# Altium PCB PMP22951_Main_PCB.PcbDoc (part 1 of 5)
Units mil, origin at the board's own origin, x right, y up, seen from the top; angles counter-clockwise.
Board outline 6643.5 x 4153.54 mil, 6 copper layers (Top Layer, Signal Layer 1, Signal Layer 2, Signal Layer 3, Signal Layer 4, Bottom Layer), stack 65.8 mil thick; 139 components, 80 nets, 687 pads, 417 vias.
Unrouted connection lines stored in the file: 2.
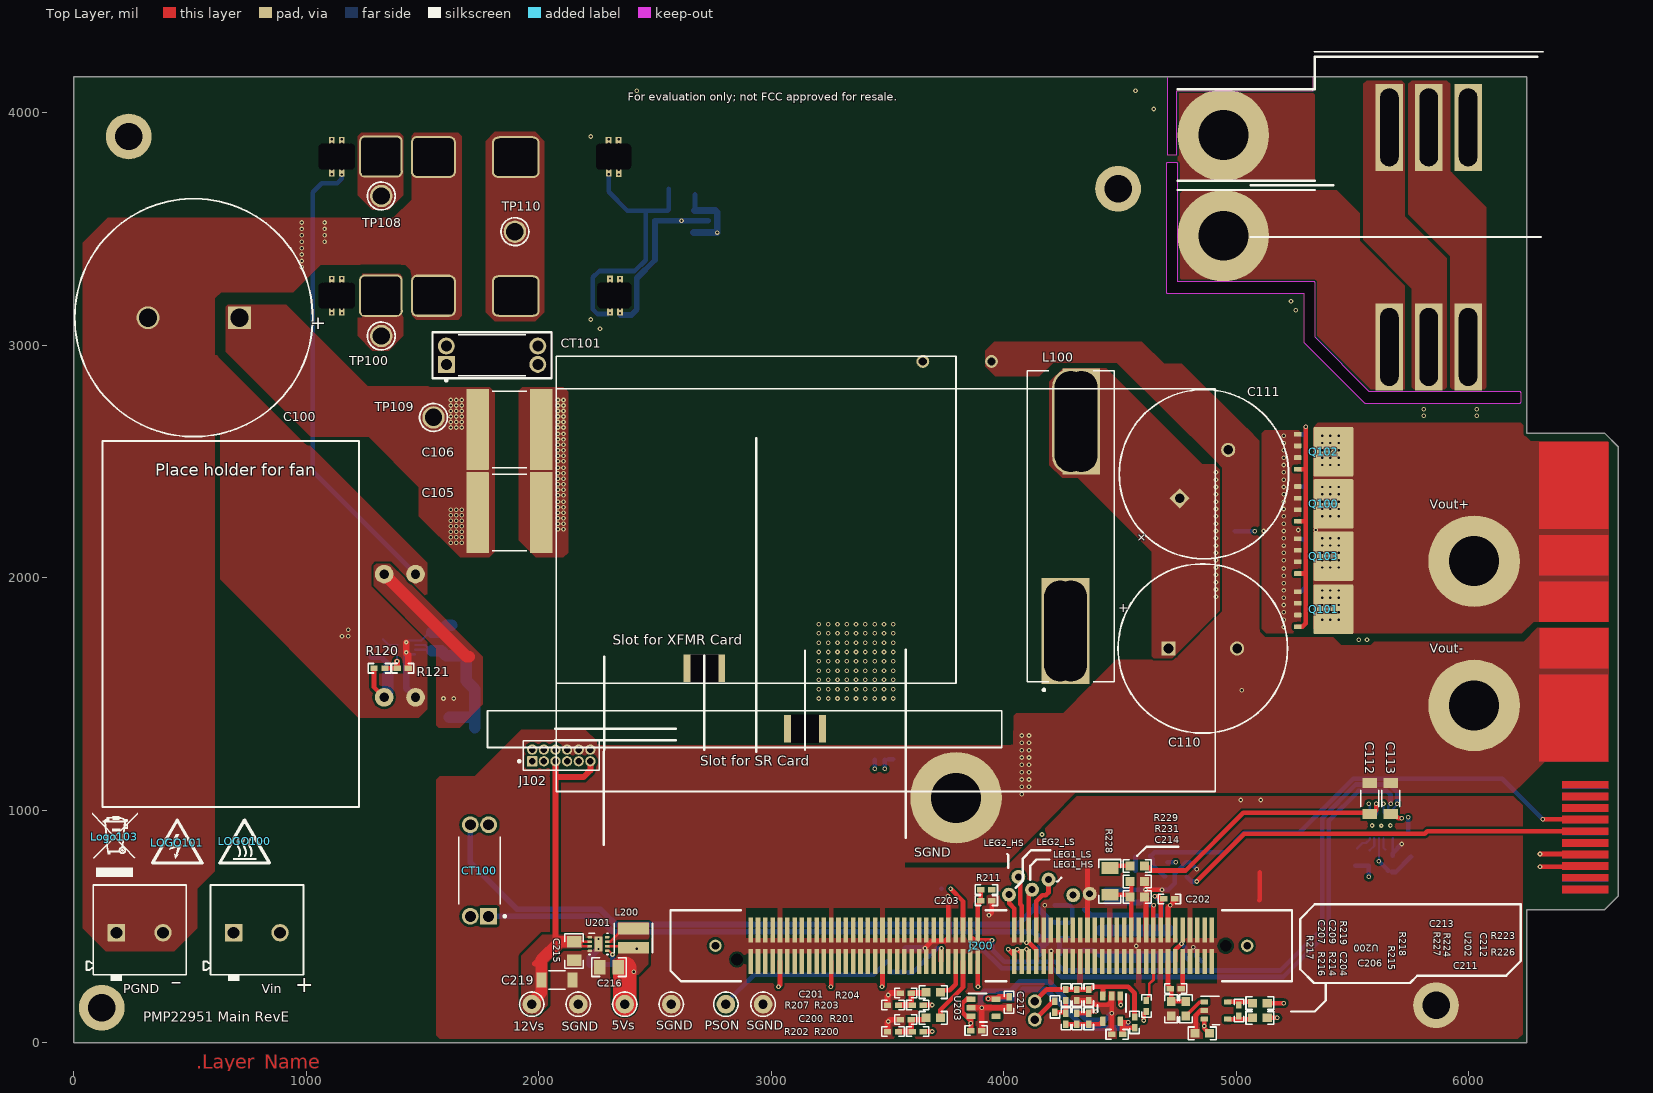
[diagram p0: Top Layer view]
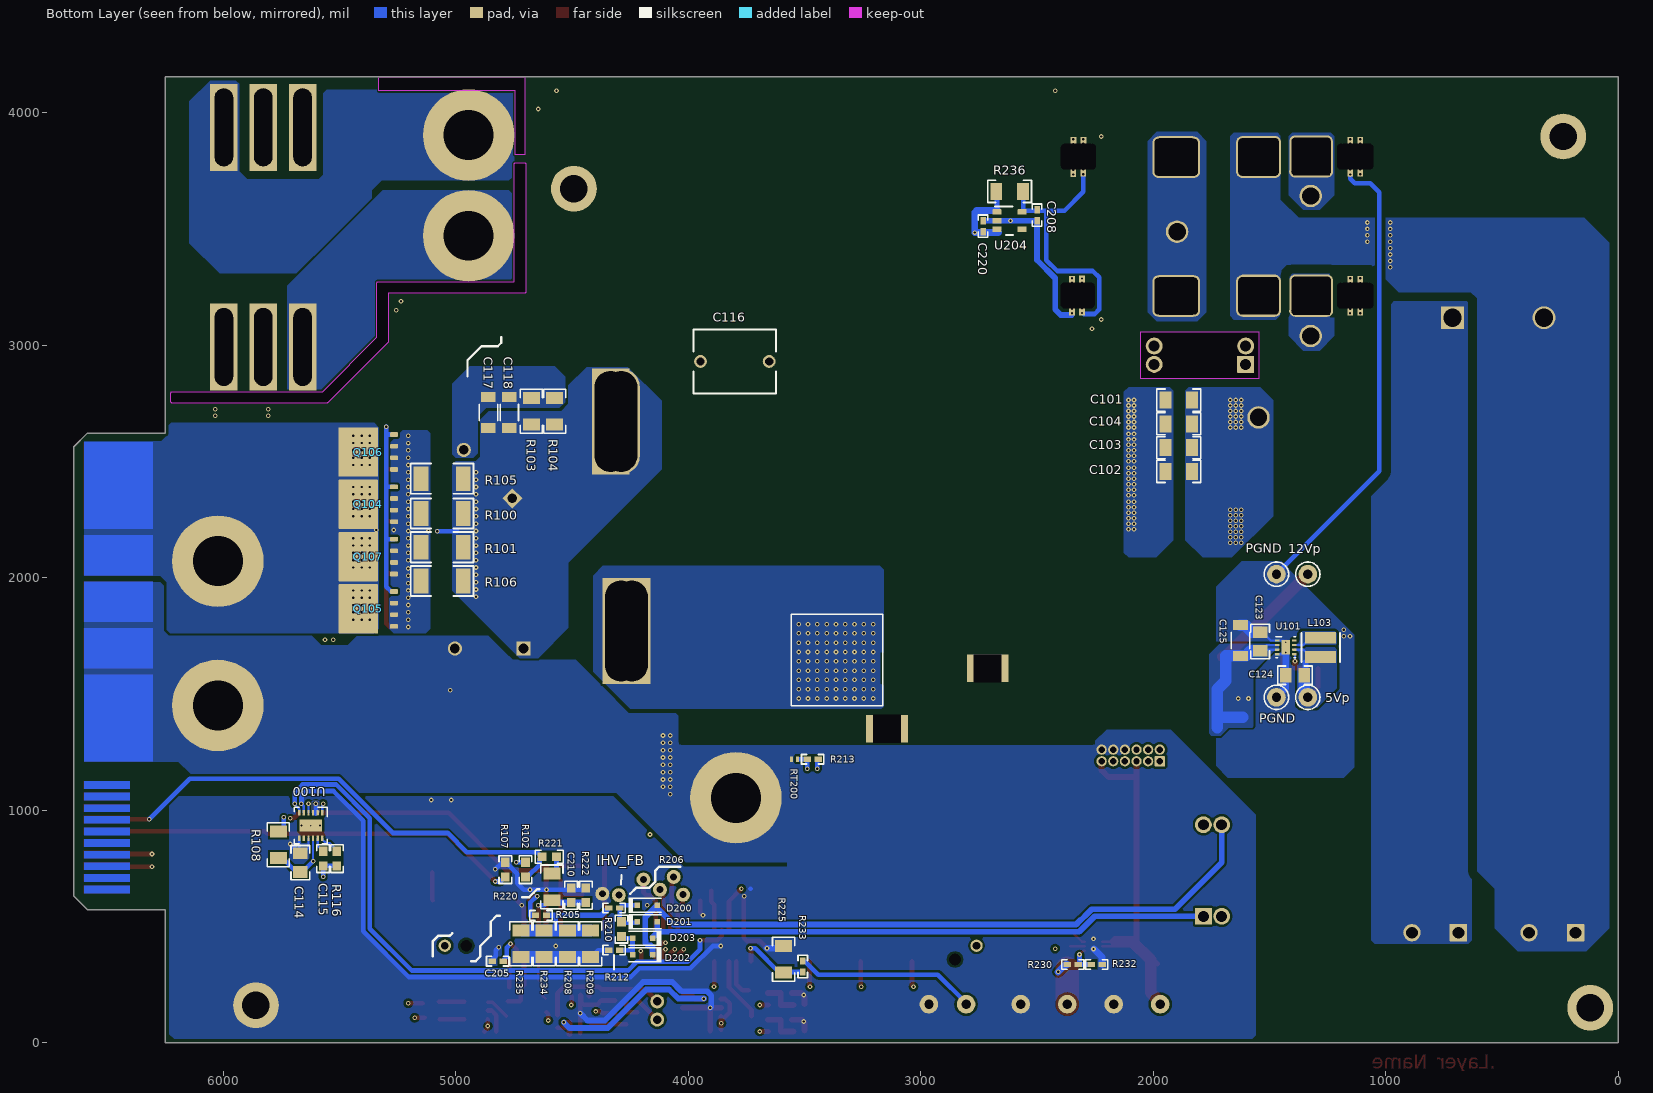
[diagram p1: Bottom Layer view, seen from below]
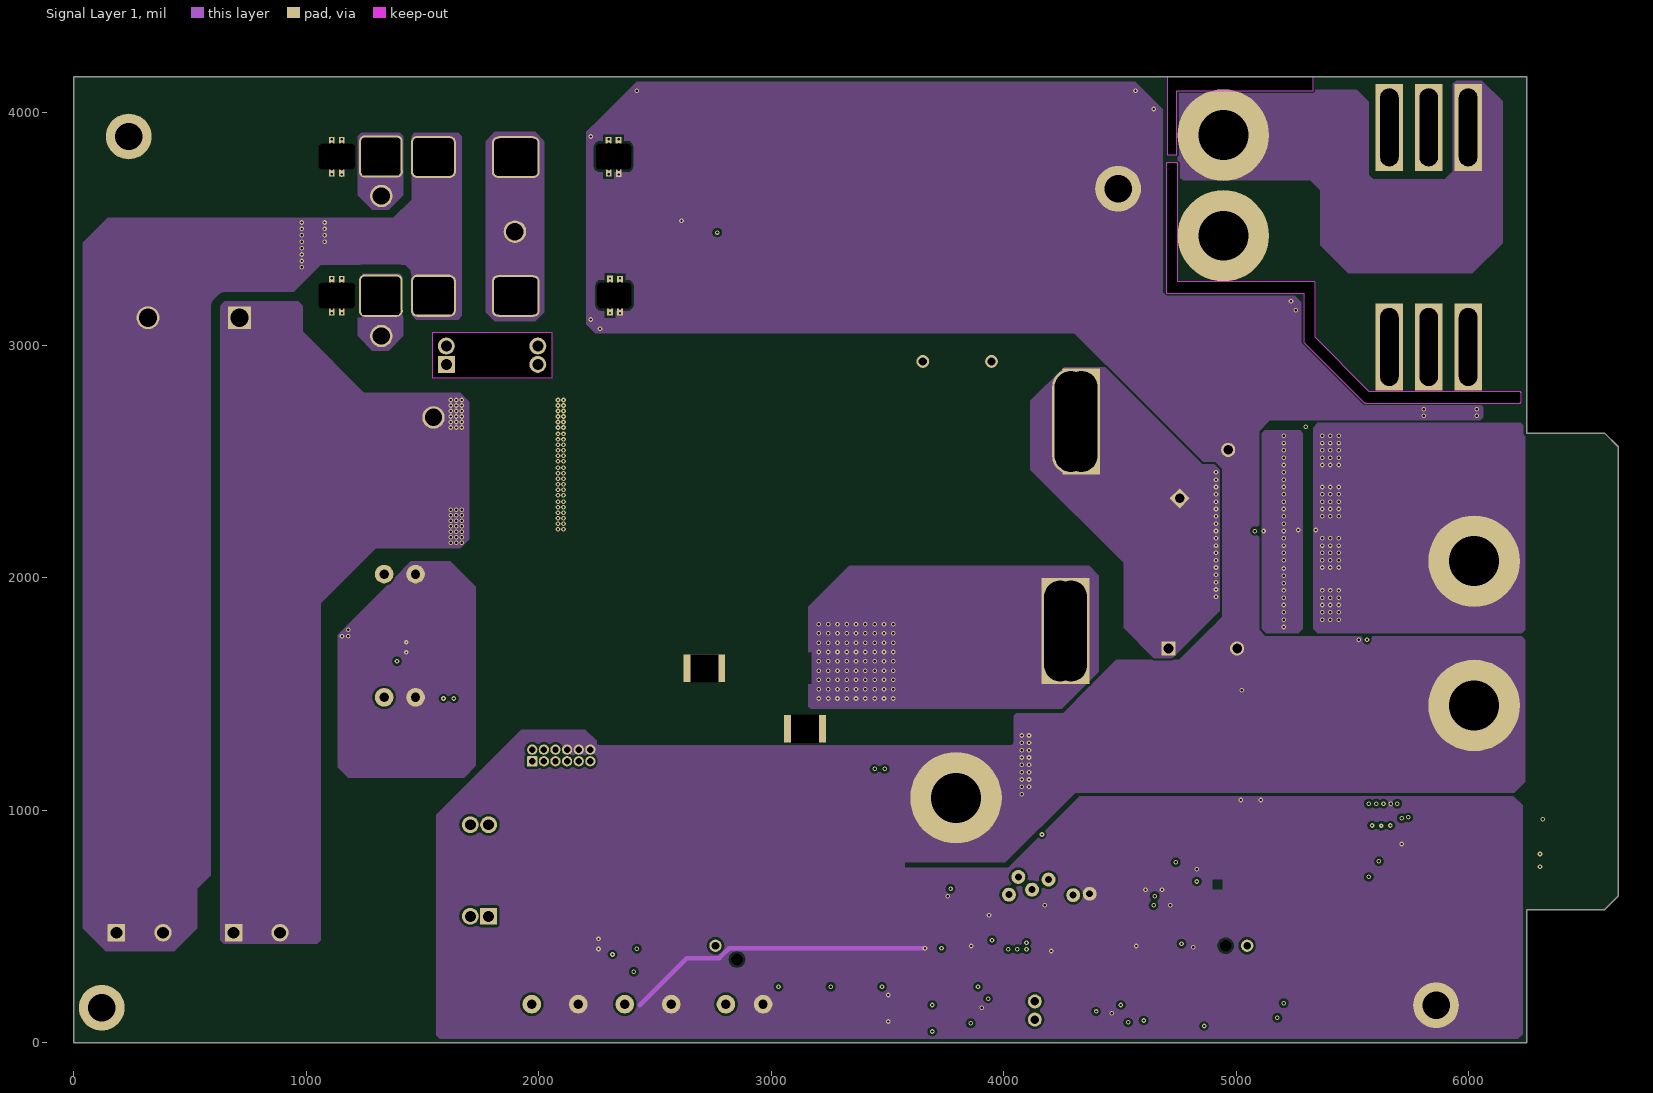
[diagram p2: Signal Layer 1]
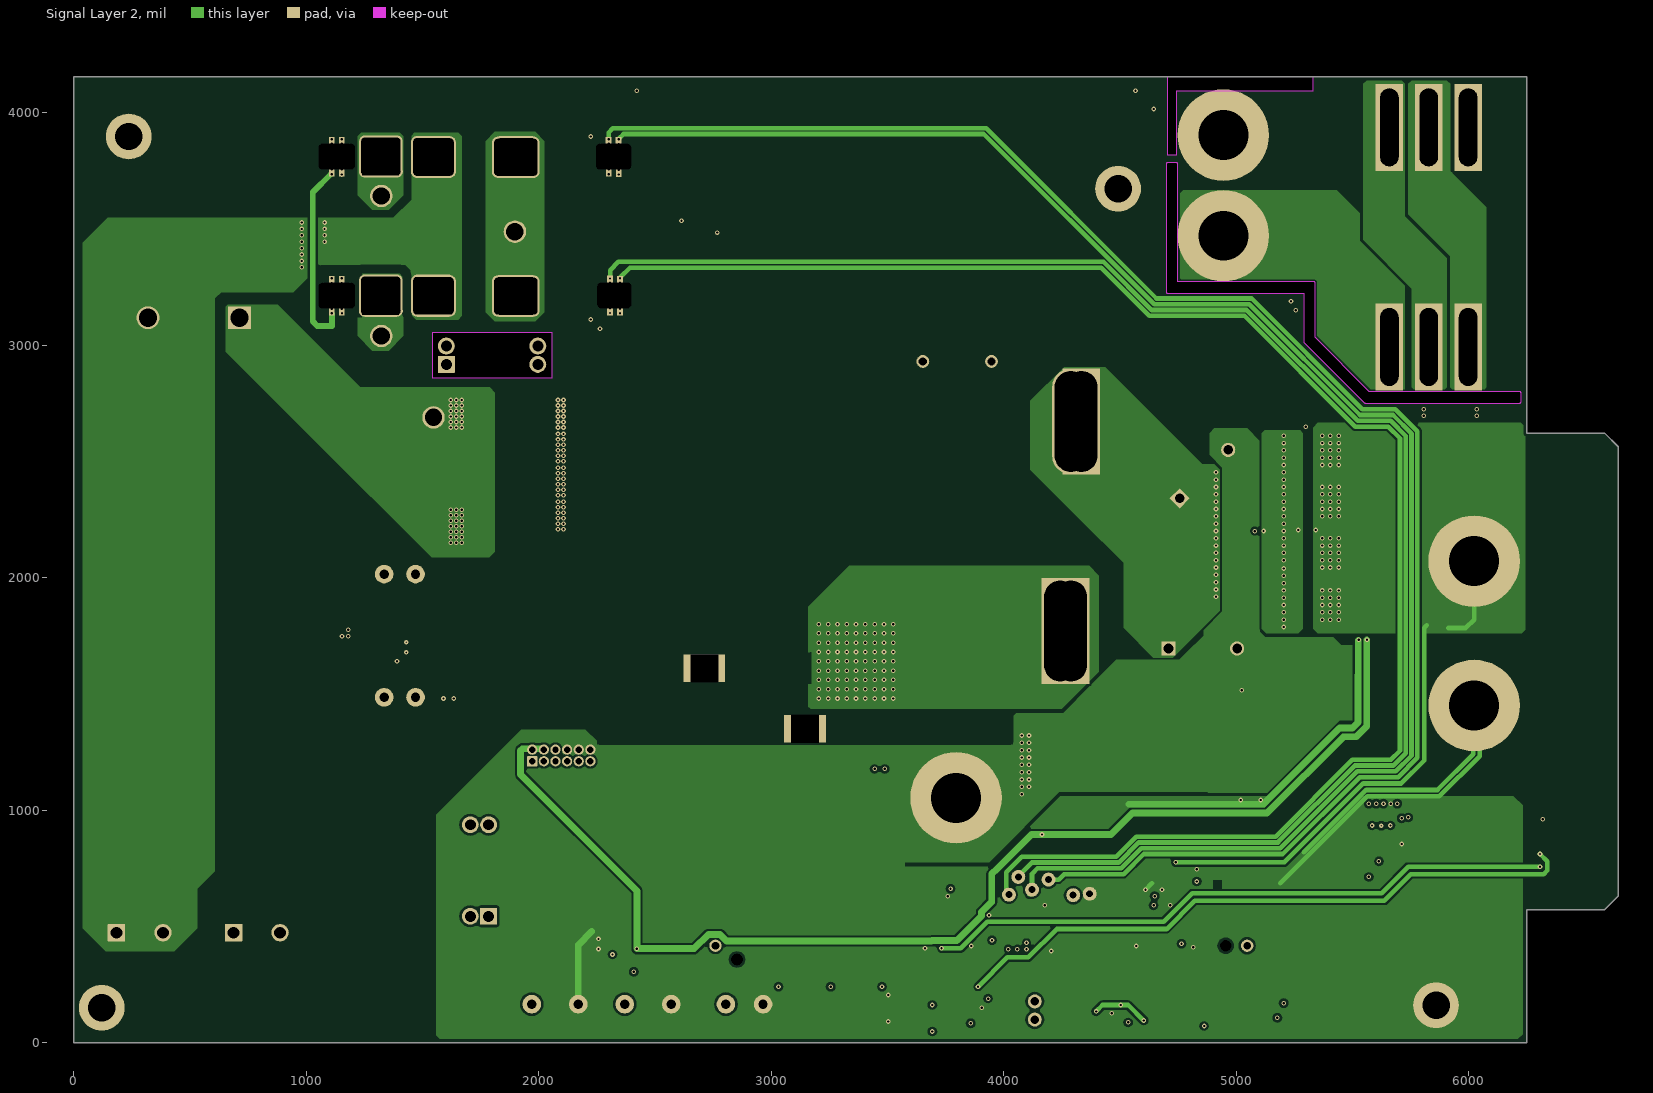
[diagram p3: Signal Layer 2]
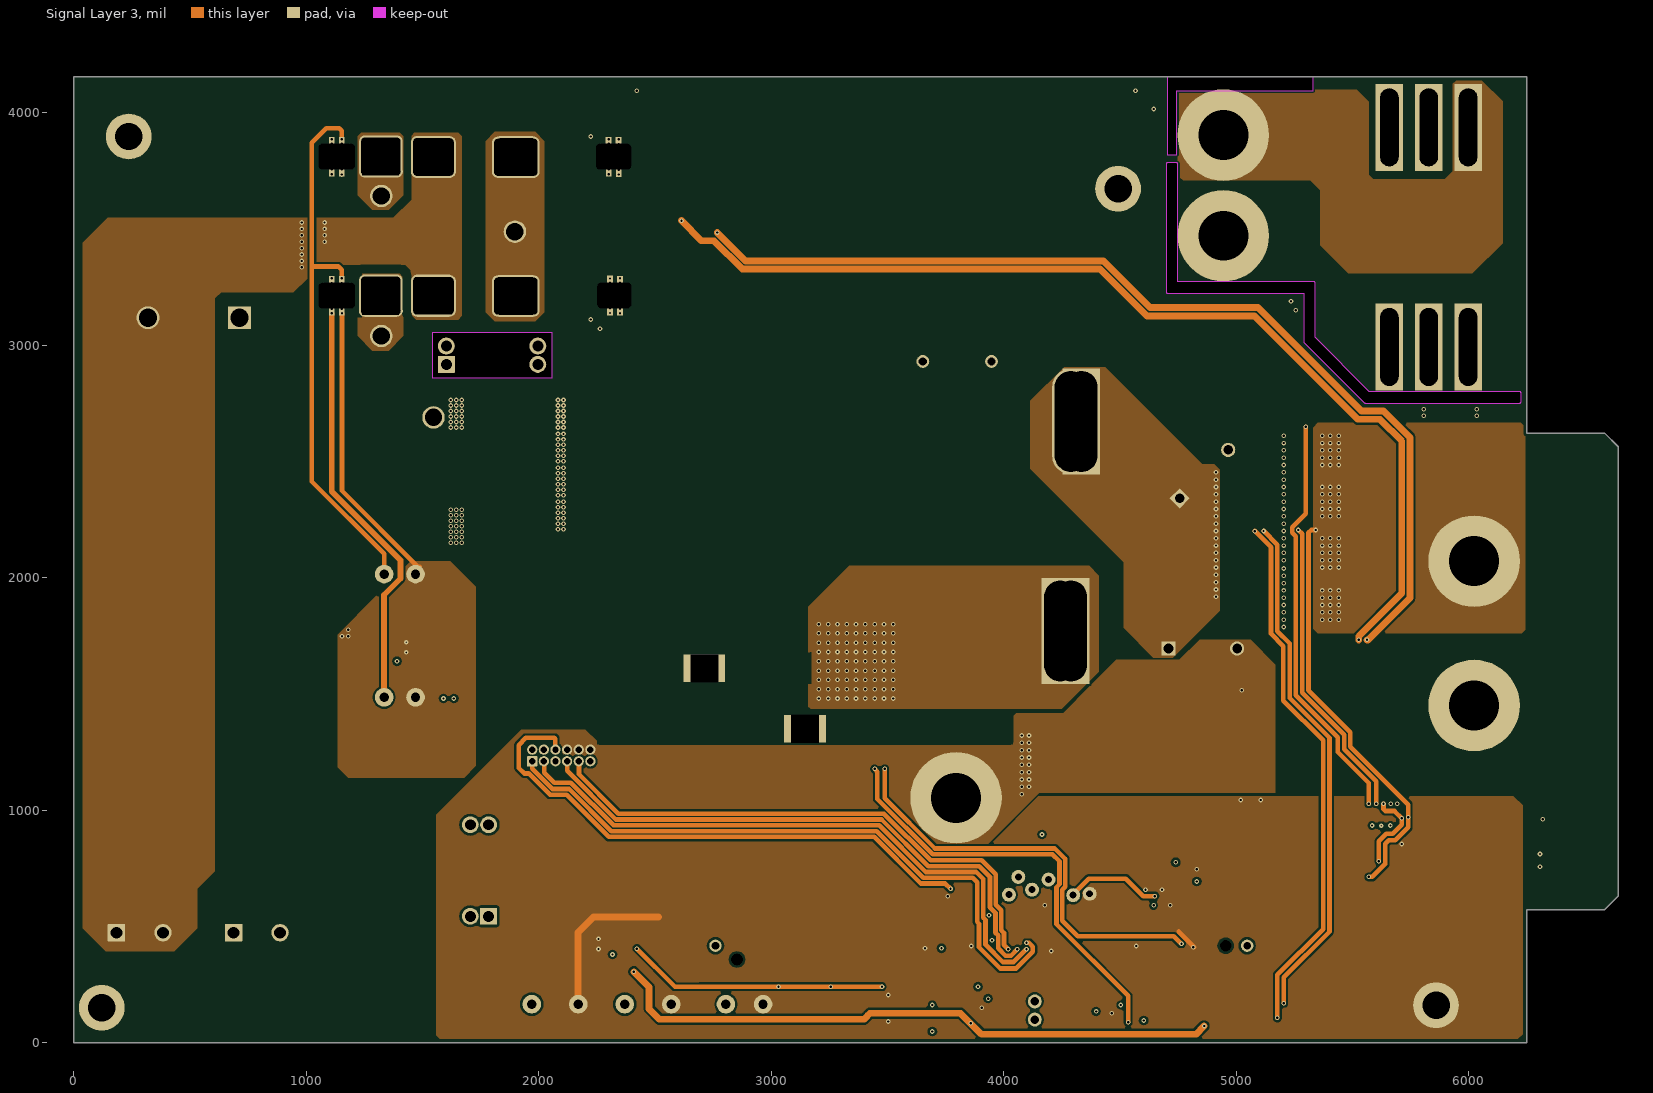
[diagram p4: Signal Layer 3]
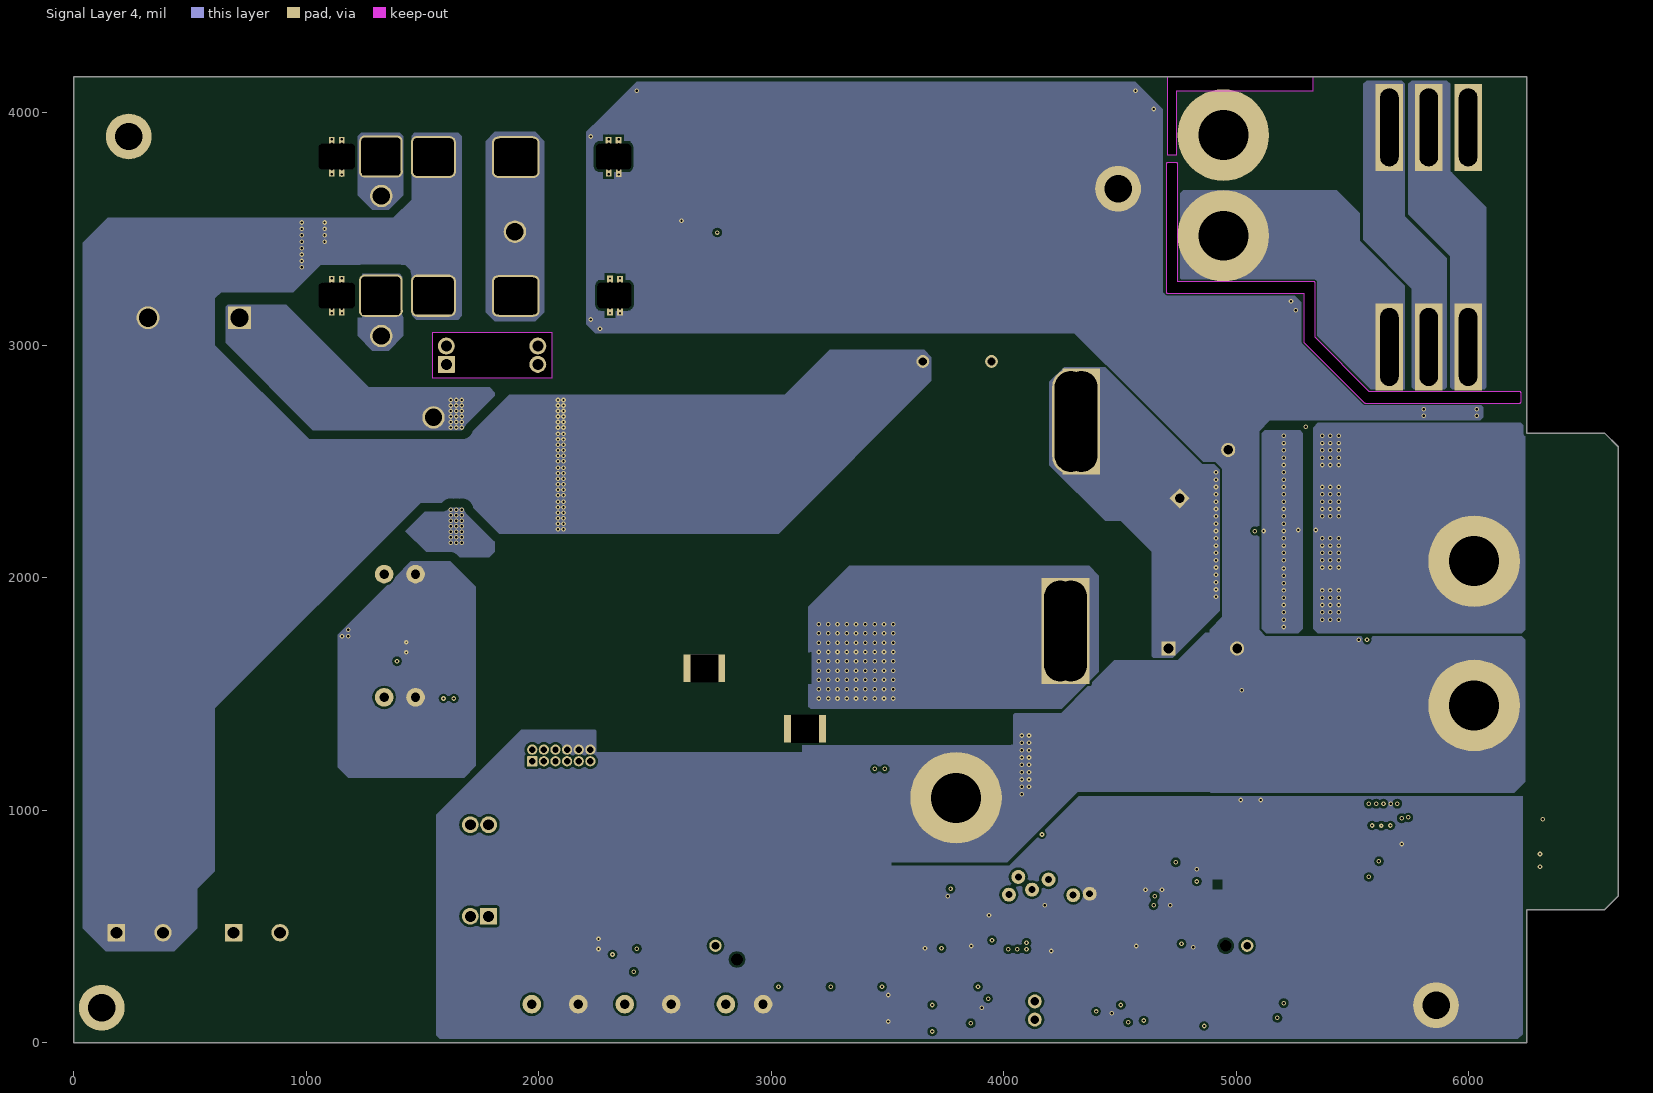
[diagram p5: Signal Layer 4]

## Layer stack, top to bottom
Top Solder: solder mask 0.4, Solder Resist, Dk 3.5
Top Layer: signal copper 2.8
Dielectric 2: prepreg 7, Dk 4.2
Signal Layer 1: signal copper 2.8
Dielectric 3: core 14, Dk 4.2
Signal Layer 2: signal copper 2.8
Dielectric1: prepreg 7, FR-4, Dk 4.2
Signal Layer 3: signal copper 2.8
Dielectric 4: core 14, Dk 4.2
Signal Layer 4: signal copper 2.8
Dielectric 5: prepreg 7, Dk 4.2
Bottom Layer: signal copper 2.8
Bottom Solder: solder mask 0.4, Solder Resist, Dk 3.5

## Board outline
0,0 0,4153.54 6250,4153.54 6250,2621.69 6584.45,2621.69 6643.5,2562.64 6643.5,630.35 6584.45,571.3 6250,571.3 6250,0
cut-out: 4704.72,3818.9 4744.09,3818.9 4744.09,4094.49 5330.71,4094.49 5330.71,4153.54 4704.72,4153.54
cut-out: 1543.31,2858.27 1543.31,3055.12 2055.12,3055.12 2055.12,2858.27
cut-out: 4699.71,3228.35 ccw(c4704.72,3228.35) 4704.72,3223.33 5290.26,3223.33 5290.26,3015.75 ccw(c5295.28,3015.75) 5291.75,3012.19 5291.73,3012.2 5551.57,2752.36 5551.56,2752.38 ccw(c5555.12,2755.91) 5555.12,2750.89 6220.47,2750.89 ccw(c6220.47,2755.91) 6225.49,2755.91 6225.49,2795.28 ccw(c6220.47,2795.28) 6220.47,2800.29 5572.94,2800.29 5339.66,3033.57 5339.66,3267.72 ccw(c5334.65,3267.72) 5334.65,3272.73 4749.11,3272.73 4749.11,3779.53 ccw(c4744.09,3779.53) 4744.09,3784.54 4704.72,3784.54 ccw(c4704.72,3779.53) 4699.71,3779.53

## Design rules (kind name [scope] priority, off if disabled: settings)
AcuteAngle [All] p1: minimum=4.50000000000000E+0001 checktracksonly=FALSE
AssemblyTestPointUsage [All] p1: valid=2
BoardOutlineClearance BoardOutlineClearance_MountingHoles [OnCopper and InComponentClass('Mounting Holes')] p1: gap=40 ignorepadtopadclearanceinfootprint=FALSE
BoardOutlineClearance BoardOutlineClearance_Poly [OnCopper and IsPoly] p2: gap=15 ignorepadtopadclearanceinfootprint=FALSE
BoardOutlineClearance [OnCopper and Not InComponentClass('Logo') and not InComponentClass('FiducialMark') and not InRegion(1000,500,4000,800) and not InPoly] p3: gap=8 ignorepadtopadclearanceinfootprint=FALSE
Clearance Clearance_5 [InNamedPolygon('SWNODE1_1') vs InNet('SWNODE1')] p1: gap=5 ignorepadtopadclearanceinfootprint=FALSE
Clearance Clearance_3 [InNamedPolygon('BOTTOM_LAYER_54V1_P128')] p2: gap=10 ignorepadtopadclearanceinfootprint=FALSE except(0: Arc-Hole Track-Hole SMDPad-Hole THPad-Hole Via-Hole Fill-Hole Poly-Hole Region-Hole Text-Hole)
Clearance Clearance_2 [InNetClass('AC') vs Not InNetClass('AC')] p3: gap=50 ignorepadtopadclearanceinfootprint=FALSE
Clearance Clearance_1 [InNetClass('HV') vs Not InNetClass('HV')] p4: gap=40 ignorepadtopadclearanceinfootprint=FALSE
Clearance Clearance_Keepouts [((IsTrack Or IsArc) And Not InPoly) And IsFree and IsKeepOut vs ((IsTrack Or IsArc) And Not InPoly) And IsFree and IsKeepOut] p5: gap=0 ignorepadtopadclearanceinfootprint=FALSE
Clearance Clearance_Poly [InPolygon] p6: gap=10 ignorepadtopadclearanceinfootprint=FALSE
Clearance Clearance_FiducialMark [IsKeepOut and InComponentClass('FiducialMark') vs IsPad and InComponentClass('FiducialMark')] p7: gap=0 ignorepadtopadclearanceinfootprint=FALSE
Clearance [All] p8: gap=4.9 ignorepadtopadclearanceinfootprint=FALSE
ComponentClearance ComponentClearance_MountingHoles_FiducialMarks [InComponentClass('Mounting Holes') vs InComponentClass('FiducialMark')] p1: gap=50 collisioncheckmode=3 verticalgap=10 showdistances=FALSE
ComponentClearance ComponentClearance_Shunt [InComponentClass('Header') vs InComponentClass('Shunt')] p2: gap=0 collisioncheckmode=3 verticalgap=0 showdistances=FALSE
ComponentClearance ComponentClearance_Logo [InComponentClass('Logo')] p3: gap=10 collisioncheckmode=3 verticalgap=10 showdistances=FALSE
ComponentClearance ComponentClearance_ScrewToNut [(HasFootprint('NY PMS 440 0025 PH')) vs (HasFootprint('Keystone_1902C'))] p4: gap=5 collisioncheckmode=3 verticalgap=10 showdistances=FALSE
ComponentClearance ComponentClearance_MountingHoles [InComponentClass('Mounting Holes')] p5: gap=50 collisioncheckmode=3 verticalgap=100000 showdistances=FALSE
ComponentClearance ComponentClearance_SmallPassives [HasFootprint('0201*') or HasFootprint('0402*') or HasFootprint('0508') or HasFootprint('0603*') or HasFootprint('0612') or HasFootprint('0805*') or HasFootprint('0815*') or HasFootprint('0830*') or HasFootprint('1206*') or HasFootprint('1210*') or HasFootprint('1808*') or HasFootprint('1812*') or HasFootprint('1825*') or HasFootprint('2010*') or HasFootprint('2220*') or HasFootprint('2225*') or HasFootprint('2512*') or HasFootprint('2728*') or HasFootprint('3518*') vs HasFootprint('0201*') or HasFootprint('0402*') or HasFootprint('0508') or HasFootprint('0603*') or HasFootprint('0612') or HasFootprint('0805*') or HasFootprint('0815*') or HasFootprint('0830*') or HasFootprint('1206*') or HasFootprint('1210*') or HasFootprint('1808*') or HasFootprint('1812*') or HasFootprint('1825*') or HasFootprint('2010*') or HasFootprint('2220*') or HasFootprint('2225*') or HasFootprint('2512*') or HasFootprint('2728*') or HasFootprint('3518*')] p6: gap=14.96 collisioncheckmode=3 verticalgap=10 showdistances=FALSE
ComponentClearance ComponentClearance_THtoSMT [IsThruComponent vs IsSMTComponent] p7: gap=10 collisioncheckmode=3 verticalgap=10 showdistances=FALSE
ComponentClearance ComponentClearance_THtoTH [IsThruComponent vs IsThruComponent] p8: gap=10 collisioncheckmode=3 verticalgap=10 showdistances=FALSE
ComponentClearance [All] p9: gap=10 collisioncheckmode=3 verticalgap=10 showdistances=FALSE
DiffPairsRouting [All] p1: maxlimit=100 minlimit=10 mostfreqgap=10 toplayer_minwidth=15 toplayer_maxwidth=15 toplayer_prefwidth=15 midlayer1_minwidth=15 midlayer1_maxwidth=15 midlayer1_prefwidth=15 midlayer2_minwidth=15 midlayer2_maxwidth=15 midlayer2_prefwidth=15 midlayer3_minwidth=15 midlayer3_maxwidth=15 midlayer3_prefwidth=15 midlayer4_minwidth=15 midlayer4_maxwidth=15 midlayer4_prefwidth=15 bottomlayer_minwidth=15 bottomlayer_maxwidth=15 bottomlayer_prefwidth=15 maxuncoupledlength=1000
FabricationTestPointUsage TestPointUsage [All] p1: valid=2 allowmultiple=FALSE
FabricationTestpoint Testpoint [All] p1: side=3 testpointundercomponent=TRUE minsize=40 maxsize=100 preferedsize=60 minholesize=0 maxholesize=40 preferedholesize=32 testpointgrid=1 allowsidetop=TRUE allowsidebottom=TRUE usegrid=TRUE gridtolerance=0.01
FanoutControl Fanout_LCC [IsLCC] p1: bgadir=Out bgaviamode=Centered fanoutstyle=Auto fanoutdirection=Alternating viagrid=1 // Fanout_LCC (Default Rule)
FanoutControl Fanout_BGA [IsBGA] p2: bgadir=Out bgaviamode=Centered fanoutstyle=Auto fanoutdirection=Alternating viagrid=1 // Fanout_BGA (Default Rule)
FanoutControl Fanout_Default [All] p4: bgadir=Out bgaviamode=Centered fanoutstyle=Auto fanoutdirection=Alternating viagrid=1 // Fanout_Default (Default Rule)
FanoutControl Fanout_Small [(CompPinCount < 5)] p5: bgadir=Out bgaviamode=Centered fanoutstyle=Auto fanoutdirection=OutThenIn viagrid=1 // Fanout_Small (Default Rule)
Height [All] p1: minheight=0 maxheight=1500 prefheight=500
HoleSize [All] p1: absolutevalues=TRUE maxlimit=500 minlimit=7.87 maxpercent=80.000 minpercent=20.000
HoleToHoleClearance [All] p1: gap=0 allowstackedmicrovias=TRUE
MinimumAnnularRing MinimumAnnularRing_ThermalPadVias [IsVia and InAnyComponent] p1: minimumring=5.91
MinimumAnnularRing [All] p2: minimumring=5
MinimumSolderMaskSliver MinimumSolderMaskSliver_Logo [InComponentClass('Logo') vs InComponentClass('Logo')] p1: minsoldermaskwidth=0.7
MinimumSolderMaskSliver [All] p2: minsoldermaskwidth=3.94
PlaneConnect [All] p1: planeconnectstyle=Relief reliefexpansion=10 reliefentries=4 reliefconductorwidth=10 reliefairgap=10
PolygonConnect PolygonConnect_68 [All vs IsNamedPolygon('12Vs') Or  IsNamedPolygon('12Vp') Or  IsNamedPolygon('SWNODE4') Or  IsNamedPolygon('VSR') Or  IsNamedPolygon('SWNODE4') Or  IsNamedPolygon('SWNODE4') Or  IsNamedPolygon('54V2') Or  IsNamedPolygon('SWNODE3') Or  IsNamedPolygon('Iout_SNS') Or  IsNamedPolygon('12Vp') Or  IsNamedPolygon('SWNODE3') Or  IsNamedPolygon('PGND') Or  IsNamedPolygon('SGND') Or  IsNamedPolygon('SWNODE3') Or  IsNamedPolygon('SWNODE4') Or  IsNamedPolygon('SGND') Or  IsNamedPolygon('5Vp') Or  IsNamedPolygon('SGND') Or  IsNamedPolygon('PGND') Or  IsNamedPolygon('SWNODE4') Or  IsNamedPolygon('Iout_SNS') Or  IsNamedPolygon('Iout_SNS') Or  IsNamedPolygon('54V1') Or  IsNamedPolygon('54V2') Or  IsNamedPolygon('SGND') Or  IsNamedPolygon('L103_1') Or  IsNamedPolygon('SGND') Or  IsNamedPolygon('VSR') Or  IsNamedPolygon('SGND') Or  IsNamedPolygon('SGND') Or  IsNamedPolygon('SGND') Or  IsNamedPolygon('54V2') Or  IsNamedPolygon('54V1') Or  IsNamedPolygon('54V1') Or  IsNamedPolygon('54V1') Or  IsNamedPolygon('54V2') Or  IsNamedPolygon('SGND') Or  IsNamedPolygon('54V2') Or  IsNamedPolygon('SWNODE4') Or  IsNamedPolygon('Iout_SNS') Or  IsNamedPolygon('SGND') Or  IsNamedPolygon('PGND') Or  IsNamedPolygon('54V1') Or  IsNamedPolygon('SGND') Or  IsNamedPolygon('SGND') Or  IsNamedPolygon('54V1') Or  IsNamedPolygon('Iout_SNS') Or  IsNamedPolygon('VSR') Or  IsNamedPolygon('SGND') Or  IsNamedPolygon('SGND') Or  IsNamedPolygon('L200_1') Or  IsNamedPolygon('54V2') Or  IsNamedPolygon('VSR') Or  IsNamedPolygon('Iout_SNS') Or  IsNamedPolygon('VSR') Or  IsNamedPolygon('5Vs') Or  IsNamedPolygon('SWNODE3') Or  IsNamedPolygon('SGND') Or  IsNamedPolygon('SWNODE3') Or  IsNamedPolygon('PGND') Or  IsNamedPolygon('SWNODE3') Or  IsNamedPolygon('SWNODE1') Or  IsNamedPolygon('SWNODE1') Or  IsNamedPolygon('SWNODE1') Or  IsNamedPolygon('VBB') Or  IsNamedPolygon('SWNODE3') Or  IsNamedPolygon('VBB') Or  IsNamedPolygon('SWNODE1') Or  IsNamedPolygon('VBB1') Or  IsNamedPolygon('VBB1') Or  IsNamedPolygon('SWNODE1') Or  IsNamedPolygon('VBB1') Or  IsNamedPolygon('SWNODE4') Or  IsNamedPolygon('SWNODE1') Or  IsNamedPolygon('VBB1') Or  IsNamedPolygon('VBB1') Or  IsNamedPolygon('SWNODE2') Or  IsNamedPolygon('VBB') Or  IsNamedPolygon('VBB1')] p1: connectstyle=Direct reliefconductorwidth=10 reliefentries=4 polygonreliefangle="90 Angle" airgapwidth=10
PolygonConnect PolygonConnect_67 [All vs IsNamedPolygon('SWNODE4') Or  IsNamedPolygon('SWNODE3') Or  IsNamedPolygon('SWNODE3') Or  IsNamedPolygon('SWNODE3') Or  IsNamedPolygon('SGND') Or  IsNamedPolygon('PGND') Or  IsNamedPolygon('SGND') Or  IsNamedPolygon('PGND') Or  IsNamedPolygon('SGND') Or  IsNamedPolygon('Iout_SNS') Or  IsNamedPolygon('VSR') Or  IsNamedPolygon('VSR') Or  IsNamedPolygon('SWNODE3') Or  IsNamedPolygon('VBB') Or  IsNamedPolygon('SWNODE4') Or  IsNamedPolygon('SWNODE4') Or  IsNamedPolygon('VSR') Or  IsNamedPolygon('Iout_SNS') Or  IsNamedPolygon('SWNODE4') Or  IsNamedPolygon('SWNODE4') Or  IsNamedPolygon('SGND') Or  IsNamedPolygon('VBB1') Or  IsNamedPolygon('SGND') Or  IsNamedPolygon('VBB') Or  IsNamedPolygon('VSR') Or  IsNamedPolygon('SGND') Or  IsNamedPolygon('VBB') Or  IsNamedPolygon('Iout_SNS') Or  IsNamedPolygon('SGND') Or  IsNamedPolygon('SGND') Or  IsNamedPolygon('SGND') Or  IsNamedPolygon('SGND') Or  IsNamedPolygon('SWNODE4') Or  IsNamedPolygon('SWNODE4') Or  IsNamedPolygon('SWNODE3') Or  IsNamedPolygon('VSR') Or  IsNamedPolygon('PGND') Or  IsNamedPolygon('SWNODE3') Or  IsNamedPolygon('SGND') Or  IsNamedPolygon('SWNODE3') Or  IsNamedPolygon('L200_1') Or  IsNamedPolygon('Iout_SNS') Or  IsNamedPolygon('SGND') Or  IsNamedPolygon('54V1') Or  IsNamedPolygon('54V1') Or  IsNamedPolygon('5Vs') Or  IsNamedPolygon('12Vp') Or  IsNamedPolygon('12Vs') Or  IsNamedPolygon('Iout_SNS') Or  IsNamedPolygon('54V2') Or  IsNamedPolygon('54V2') Or  IsNamedPolygon('54V2') Or  IsNamedPolygon('12Vp') Or  IsNamedPolygon('54V2') Or  IsNamedPolygon('SGND') Or  IsNamedPolygon('54V2') Or  IsNamedPolygon('54V2') Or  IsNamedPolygon('54V1') Or  IsNamedPolygon('54V1') Or  IsNamedPolygon('54V1') Or  IsNamedPolygon('5Vp') Or  IsNamedPolygon('54V1') Or  IsNamedPolygon('SGND') Or  IsNamedPolygon('SGND') Or  IsNamedPolygon('L103_1') Or  IsNamedPolygon('Iout_SNS') Or  IsNamedPolygon('PGND')] p2: connectstyle=Direct reliefconductorwidth=10 reliefentries=4 polygonreliefangle="90 Angle" airgapwidth=10
PolygonConnect PolygonConnect_66 [All vs IsNamedPolygon('RTN') Or  IsNamedPolygon('SWNODE4') Or  IsNamedPolygon('SWNODE3') Or  IsNamedPolygon('12Vs') Or  IsNamedPolygon('SWNODE3') Or  IsNamedPolygon('SGND') Or  IsNamedPolygon('VSR') Or  IsNamedPolygon('RTN') Or  IsNamedPolygon('SWNODE3') Or  IsNamedPolygon('SWNODE4') Or  IsNamedPolygon('SWNODE4') Or  IsNamedPolygon('SWNODE4') Or  IsNamedPolygon('SWNODE3') Or  IsNamedPolygon('SWNODE4') Or  IsNamedPolygon('SWNODE3') Or  IsNamedPolygon('15Vs') Or  IsNamedPolygon('SWNODE4') Or  IsNamedPolygon('SWNODE3') Or  IsNamedPolygon('12Vp') Or  IsNamedPolygon('SWNODE3') Or  IsNamedPolygon('RTN') Or  IsNamedPolygon('SWNODE4') Or  IsNamedPolygon('SWNODE3') Or  IsNamedPolygon('SWNODE4') Or  IsNamedPolygon('SWNODE3') Or  IsNamedPolygon('SWNODE4') Or  IsNamedPolygon('SWNODE4') Or  IsNamedPolygon('SWNODE4') Or  IsNamedPolygon('SWNODE4') Or  IsNamedPolygon('SWNODE4') Or  IsNamedPolygon('SWNODE3') Or  IsNamedPolygon('RTN') Or  IsNamedPolygon('L103_1') Or  IsNamedPolygon('SWNODE4') Or  IsNamedPolygon('SWNODE3') Or  IsNamedPolygon('SWNODE4') Or  IsNamedPolygon('12Vp') Or  IsNamedPolygon('PGND') Or  IsNamedPolygon('VSR') Or  IsNamedPolygon('SGND') Or  IsNamedPolygon('SWNODE4') Or  IsNamedPolygon('SWNODE4') Or  IsNamedPolygon('SWNODE3') Or  IsNamedPolygon('SWNODE3') Or  IsNamedPolygon('SWNODE4') Or  IsNamedPolygon('SWNODE4') Or  IsNamedPolygon('SWNODE3') Or  IsNamedPolygon('ACLGND') Or  IsNamedPolygon('5Vp') Or  IsNamedPolygon('SWNODE3') Or  IsNamedPolygon('VSR') Or  IsNamedPolygon('SWNODE3') Or  IsNamedPolygon('SWNODE4') Or  IsNamedPolygon('RTN') Or  IsNamedPolygon('SWNODE4') Or  IsNamedPolygon('SWNODE3') Or  IsNamedPolygon('Iout_SNS') Or  IsNamedPolygon('Iout_SNS') Or  IsNamedPolygon('SWNODE2') Or  IsNamedPolygon('VSR') Or  IsNamedPolygon('T100_1') Or  IsNamedPolygon('VSR') Or  IsNamedPolygon('NetT100_1') Or  IsNamedPolygon('SWNODE3') Or  IsNamedPolygon('NetT100_1') Or  IsNamedPolygon('RTN') Or  IsNamedPolygon('54V1') Or  IsNamedPolygon('SGND') Or  IsNamedPolygon('VSR') Or  IsNamedPolygon('SWNODE2') Or  IsNamedPolygon('VBB') Or  IsNamedPolygon('SWNODE1_1') Or  IsNamedPolygon('54V2') Or  IsNamedPolygon('SWNODE4') Or  IsNamedPolygon('54V2') Or  IsNamedPolygon('SGND') Or  IsNamedPolygon('SWNODE2_1') Or  IsNamedPolygon('SWNODE3') Or  IsNamedPolygon('Iout_SNS') Or  IsNamedPolygon('54V1') Or  IsNamedPolygon('54V2') Or  IsNamedPolygon('SGND') Or  IsNamedPolygon('VSR') Or  IsNamedPolygon('54V1') Or  IsNamedPolygon('5Vs') Or  IsNamedPolygon('L200_1') Or  IsNamedPolygon('SWNODE3') Or  IsNamedPolygon('PGND') Or  IsNamedPolygon('PGND') Or  IsNamedPolygon('54V2') Or  IsNamedPolygon('SWNODE1_1') Or  IsNamedPolygon('T100_2') Or  IsNamedPolygon('SWNODE4') Or  IsNamedPolygon('SWNODE2') Or  IsNamedPolygon('SWNODE3') Or  IsNamedPolygon('54V2') Or  IsNamedPolygon('SWNODE3') Or  IsNamedPolygon('SWNODE3') Or  IsNamedPolygon('Iout_SNS') Or  IsNamedPolygon('PGND') Or  IsNamedPolygon('SWNODE4') Or  IsNamedPolygon('SGND') Or  IsNamedPolygon('SWNODE4') Or  IsNamedPolygon('SWNODE4') Or  IsNamedPolygon('SWNODE2') Or  IsNamedPolygon('SGND') Or  IsNamedPolygon('54V1') Or  IsNamedPolygon('T100_1') Or  IsNamedPolygon('SGND') Or  IsNamedPolygon('SWNODE2') Or  IsNamedPolygon('54V2') Or  IsNamedPolygon('Iout_SNS') Or  IsNamedPolygon('54V1') Or  IsNamedPolygon('SGND') Or  IsNamedPolygon('SGND') Or  IsNamedPolygon('SWNODE2') Or  IsNamedPolygon('Iout_SNS') Or  IsNamedPolygon('SWNODE4') Or  IsNamedPolygon('T100_2') Or  IsNamedPolygon('SGND') Or  IsNamedPolygon('SWNODE4') Or  IsNamedPolygon('SGND') Or  IsNamedPolygon('SGND') Or  IsNamedPolygon('54V1') Or  IsNamedPolygon('SWNODE2_1') Or  IsNamedPolygon('VSR') Or  IsNamedPolygon('SWNODE3')] p3: connectstyle=Direct reliefconductorwidth=10 reliefentries=4 polygonreliefangle="90 Angle" airgapwidth=10
PolygonConnect PolygonConnect_65 [All vs IsNamedPolygon('SWNODE4') Or  IsNamedPolygon('SWNODE3') Or  IsNamedPolygon('Iout_SNS') Or  IsNamedPolygon('54V1') Or  IsNamedPolygon('54V1') Or  IsNamedPolygon('SGND') Or  IsNamedPolygon('SWNODE4') Or  IsNamedPolygon('SWNODE3') Or  IsNamedPolygon('L200_1') Or  IsNamedPolygon('SWNODE3') Or  IsNamedPolygon('VSR') Or  IsNamedPolygon('SGND') Or  IsNamedPolygon('SWNODE3') Or  IsNamedPolygon('SWNODE3') Or  IsNamedPolygon('SGND') Or  IsNamedPolygon('SWNODE3') Or  IsNamedPolygon('Iout_SNS') Or  IsNamedPolygon('SWNODE4') Or  IsNamedPolygon('SWNODE4') Or  IsNamedPolygon('SWNODE2') Or  IsNamedPolygon('NetT100_1') Or  IsNamedPolygon('SWNODE4') Or  IsNamedPolygon('SWNODE3') Or  IsNamedPolygon('SWNODE4') Or  IsNamedPolygon('SWNODE3') Or  IsNamedPolygon('SWNODE1_1') Or  IsNamedPolygon('SWNODE4') Or  IsNamedPolygon('T100_2') Or  IsNamedPolygon('RTN') Or  IsNamedPolygon('SGND') Or  IsNamedPolygon('SWNODE3') Or  IsNamedPolygon('RTN') Or  IsNamedPolygon('SWNODE2') Or  IsNamedPolygon('SWNODE2') Or  IsNamedPolygon('SGND') Or  IsNamedPolygon('SWNODE3') Or  IsNamedPolygon('SGND') Or  IsNamedPolygon('SWNODE4') Or  IsNamedPolygon('SWNODE2') Or  IsNamedPolygon('SWNODE3') Or  IsNamedPolygon('SWNODE3') Or  IsNamedPolygon('SWNODE3') Or  IsNamedPolygon('SWNODE4') Or  IsNamedPolygon('SWNODE4') Or  IsNamedPolygon('VSR') Or  IsNamedPolygon('SGND') Or  IsNamedPolygon('SWNODE3') Or  IsNamedPolygon('SWNODE4') Or  IsNamedPolygon('SWNODE4') Or  IsNamedPolygon('SWNODE1_1') Or  IsNamedPolygon('RTN') Or  IsNamedPolygon('ACLGND') Or  IsNamedPolygon('SWNODE4') Or  IsNamedPolygon('RTN') Or  IsNamedPolygon('SWNODE4') Or  IsNamedPolygon('SWNODE3') Or  IsNamedPolygon('T100_1') Or  IsNamedPolygon('SWNODE3') Or  IsNamedPolygon('VSR') Or  IsNamedPolygon('VBB') Or  IsNamedPolygon('PGND') Or  IsNamedPolygon('SWNODE3') Or  IsNamedPolygon('T100_2') Or  IsNamedPolygon('SWNODE3') Or  IsNamedPolygon('12Vs') Or  IsNamedPolygon('54V2') Or  IsNamedPolygon('SGND') Or  IsNamedPolygon('PGND') Or  IsNamedPolygon('54V1') Or  IsNamedPolygon('54V2') Or  IsNamedPolygon('54V1') Or  IsNamedPolygon('SWNODE3') Or  IsNamedPolygon('PGND') Or  IsNamedPolygon('VSR') Or  IsNamedPolygon('Iout_SNS') Or  IsNamedPolygon('SWNODE2') Or  IsNamedPolygon('Iout_SNS') Or  IsNamedPolygon('54V1') Or  IsNamedPolygon('SWNODE4') Or  IsNamedPolygon('54V2') Or  IsNamedPolygon('SWNODE4') Or  IsNamedPolygon('SGND') Or  IsNamedPolygon('15Vs') Or  IsNamedPolygon('RTN') Or  IsNamedPolygon('SWNODE4') Or  IsNamedPolygon('SWNODE3') Or  IsNamedPolygon('SWNODE4') Or  IsNamedPolygon('SGND') Or  IsNamedPolygon('VSR') Or  IsNamedPolygon('SWNODE4') Or  IsNamedPolygon('Iout_SNS') Or  IsNamedPolygon('VSR') Or  IsNamedPolygon('T100_1') Or  IsNamedPolygon('SGND') Or  IsNamedPolygon('SWNODE4') Or  IsNamedPolygon('NetT100_1') Or  IsNamedPolygon('SWNODE3') Or  IsNamedPolygon('RTN') Or  IsNamedPolygon('SWNODE2_1') Or  IsNamedPolygon('5Vs') Or  IsNamedPolygon('Iout_SNS') Or  IsNamedPolygon('SWNODE4') Or  IsNamedPolygon('54V2') Or  IsNamedPolygon('54V2') Or  IsNamedPolygon('SWNODE4') Or  IsNamedPolygon('SWNODE4') Or  IsNamedPolygon('SGND') Or  IsNamedPolygon('SWNODE4') Or  IsNamedPolygon('SGND') Or  IsNamedPolygon('SWNODE4') Or  IsNamedPolygon('SWNODE4') Or  IsNamedPolygon('54V1') Or  IsNamedPolygon('VSR') Or  IsNamedPolygon('SWNODE3') Or  IsNamedPolygon('SWNODE4') Or  IsNamedPolygon('54V2') Or  IsNamedPolygon('SWNODE2_1') Or  IsNamedPolygon('SWNODE3') Or  IsNamedPolygon('SWNODE3') Or  IsNamedPolygon('SWNODE4') Or  IsNamedPolygon('SWNODE2') Or  IsNamedPolygon('VSR')] p4: connectstyle=Direct reliefconductorwidth=10 reliefentries=4 polygonreliefangle="90 Angle" airgapwidth=10
PolygonConnect PolygonConnect_64 [All vs IsNamedPolygon('SWNODE2') Or  IsNamedPolygon('SWNODE4') Or  IsNamedPolygon('SWNODE4') Or  IsNamedPolygon('SWNODE4') Or  IsNamedPolygon('54V2') Or  IsNamedPolygon('T100_2') Or  IsNamedPolygon('Iout_SNS') Or  IsNamedPolygon('SWNODE2') Or  IsNamedPolygon('SWNODE3') Or  IsNamedPolygon('T100_2') Or  IsNamedPolygon('SWNODE4') Or  IsNamedPolygon('SWNODE4') Or  IsNamedPolygon('SWNODE3') Or  IsNamedPolygon('SWNODE4') Or  IsNamedPolygon('Iout_SNS') Or  IsNamedPolygon('SWNODE4') Or  IsNamedPolygon('SWNODE4') Or  IsNamedPolygon('ACLGND') Or  IsNamedPolygon('SWNODE1_1') Or  IsNamedPolygon('SWNODE3') Or  IsNamedPolygon('VSR') Or  IsNamedPolygon('SWNODE3') Or  IsNamedPolygon('VSR') Or  IsNamedPolygon('SWNODE4') Or  IsNamedPolygon('SWNODE3') Or  IsNamedPolygon('SWNODE3') Or  IsNamedPolygon('Iout_SNS') Or  IsNamedPolygon('SWNODE4') Or  IsNamedPolygon('SGND') Or  IsNamedPolygon('SWNODE1_1') Or  IsNamedPolygon('L200_1') Or  IsNamedPolygon('SWNODE3') Or  IsNamedPolygon('SWNODE4') Or  IsNamedPolygon('SWNODE4') Or  IsNamedPolygon('SWNODE3') Or  IsNamedPolygon('SWNODE4') Or  IsNamedPolygon('Iout_SNS') Or  IsNamedPolygon('PGND') Or  IsNamedPolygon('T100_1') Or  IsNamedPolygon('T100_1') Or  IsNamedPolygon('VSR') Or  IsNamedPolygon('54V1') Or  IsNamedPolygon('SWNODE4') Or  IsNamedPolygon('SWNODE3') Or  IsNamedPolygon('SWNODE4') Or  IsNamedPolygon('SGND') Or  IsNamedPolygon('SWNODE3') Or  IsNamedPolygon('SGND') Or  IsNamedPolygon('54V2') Or  IsNamedPolygon('54V1') Or  IsNamedPolygon('54V1') Or  IsNamedPolygon('SWNODE2') Or  IsNamedPolygon('SGND') Or  IsNamedPolygon('SGND') Or  IsNamedPolygon('SWNODE4') Or  IsNamedPolygon('VSR') Or  IsNamedPolygon('NetT100_1') Or  IsNamedPolygon('PGND') Or  IsNamedPolygon('SWNODE3') Or  IsNamedPolygon('VBB') Or  IsNamedPolygon('54V2') Or  IsNamedPolygon('SWNODE3') Or  IsNamedPolygon('SWNODE3') Or  IsNamedPolygon('54V2') Or  IsNamedPolygon('SGND') Or  IsNamedPolygon('VSR') Or  IsNamedPolygon('SGND') Or  IsNamedPolygon('SWNODE4') Or  IsNamedPolygon('54V1') Or  IsNamedPolygon('SWNODE3') Or  IsNamedPolygon('SWNODE2') Or  IsNamedPolygon('SWNODE3') Or  IsNamedPolygon('54V2') Or  IsNamedPolygon('RTN') Or  IsNamedPolygon('SWNODE4') Or  IsNamedPolygon('RTN') Or  IsNamedPolygon('SWNODE2_1') Or  IsNamedPolygon('SGND') Or  IsNamedPolygon('PGND') Or  IsNamedPolygon('SWNODE3') Or  IsNamedPolygon('SGND') Or  IsNamedPolygon('VSR') Or  IsNamedPolygon('SWNODE4') Or  IsNamedPolygon('SWNODE2') Or  IsNamedPolygon('SWNODE3') Or  IsNamedPolygon('SWNODE3') Or  IsNamedPolygon('SWNODE3') Or  IsNamedPolygon('SWNODE3') Or  IsNamedPolygon('VSR') Or  IsNamedPolygon('SWNODE3') Or  IsNamedPolygon('SWNODE3') Or  IsNamedPolygon('SWNODE4') Or  IsNamedPolygon('SWNODE4') Or  IsNamedPolygon('SWNODE4') Or  IsNamedPolygon('SGND') Or  IsNamedPolygon('SWNODE4') Or  IsNamedPolygon('SWNODE2_1') Or  IsNamedPolygon('VSR') Or  IsNamedPolygon('54V2') Or  IsNamedPolygon('SWNODE4') Or  IsNamedPolygon('SWNODE2') Or  IsNamedPolygon('Iout_SNS') Or  IsNamedPolygon('5Vs') Or  IsNamedPolygon('SWNODE3') Or  IsNamedPolygon('SWNODE4') Or  IsNamedPolygon('Iout_SNS') Or  IsNamedPolygon('SWNODE4') Or  IsNamedPolygon('SWNODE4') Or  IsNamedPolygon('54V1') Or  IsNamedPolygon('SGND') Or  IsNamedPolygon('SWNODE4') Or  IsNamedPolygon('RTN') Or  IsNamedPolygon('SWNODE3') Or  IsNamedPolygon('RTN') Or  IsNamedPolygon('NetT100_1') Or  IsNamedPolygon('SGND') Or  IsNamedPolygon('RTN') Or  IsNamedPolygon('RTN') Or  IsNamedPolygon('54V1')] p5: connectstyle=Direct reliefconductorwidth=10 reliefentries=4 polygonreliefangle="90 Angle" airgapwidth=10
PolygonConnect PolygonConnect_63 [All vs IsNamedPolygon('VBB') Or  IsNamedPolygon('54V2') Or  IsNamedPolygon('NetT100_2') Or  IsNamedPolygon('VSR') Or  IsNamedPolygon('SWNODE3') Or  IsNamedPolygon('VSR') Or  IsNamedPolygon('NetT100_2') Or  IsNamedPolygon('54V1') Or  IsNamedPolygon('SWNODE3') Or  IsNamedPolygon('54V2') Or  IsNamedPolygon('54V1') Or  IsNamedPolygon('Iout_SNS') Or  IsNamedPolygon('VSR') Or  IsNamedPolygon('SWNODE2') Or  IsNamedPolygon('NetT100_1') Or  IsNamedPolygon('SWNODE4') Or  IsNamedPolygon('54V2') Or  IsNamedPolygon('SWNODE4') Or  IsNamedPolygon('NetT100_1') Or  IsNamedPolygon('NetT100_1') Or  IsNamedPolygon('54V1') Or  IsNamedPolygon('SWNODE3') Or  IsNamedPolygon('VSR') Or  IsNamedPolygon('NetT100_1') Or  IsNamedPolygon('SWNODE4') Or  IsNamedPolygon('SWNODE4') Or  IsNamedPolygon('SWNODE3') Or  IsNamedPolygon('NetT100_2') Or  IsNamedPolygon('NetT100_2') Or  IsNamedPolygon('VSR') Or  IsNamedPolygon('SWNODE4') Or  IsNamedPolygon('NetT100_2') Or  IsNamedPolygon('SWNODE4') Or  IsNamedPolygon('NetT100_2') Or  IsNamedPolygon('Iout_SNS') Or  IsNamedPolygon('PGND') Or  IsNamedPolygon('NetT100_1') Or  IsNamedPolygon('SWNODE3') Or  IsNamedPolygon('54V2') Or  IsNamedPolygon('NetT100_1') Or  IsNamedPolygon('SWNODE3') Or  IsNamedPolygon('VSR') Or  IsNamedPolygon('T100_1') Or  IsNamedPolygon('54V1') Or  IsNamedPolygon('SWNODE2_1') Or  IsNamedPolygon('L200_1') Or  IsNamedPolygon('SWNODE2') Or  IsNamedPolygon('54V1') Or  IsNamedPolygon('SGND') Or  IsNamedPolygon('SGND') Or  IsNamedPolygon('SWNODE4') Or  IsNamedPolygon('SWNODE4') Or  IsNamedPolygon('SGND') Or  IsNamedPolygon('54V1') Or  IsNamedPolygon('SWNODE4') Or  IsNamedPolygon('SGND') Or  IsNamedPolygon('SGND') Or  IsNamedPolygon('SWNODE2') Or  IsNamedPolygon('5Vs') Or  IsNamedPolygon('SGND') Or  IsNamedPolygon('Iout_SNS') Or  IsNamedPolygon('PGND') Or  IsNamedPolygon('SGND') Or  IsNamedPolygon('Iout_SNS') Or  IsNamedPolygon('PGND') Or  IsNamedPolygon('Iout_SNS') Or  IsNamedPolygon('SWNODE3') Or  IsNamedPolygon('SWNODE4') Or  IsNamedPolygon('SWNODE3') Or  IsNamedPolygon('SWNODE3') Or  IsNamedPolygon('SWNODE1_1') Or  IsNamedPolygon('SWNODE1_1') Or  IsNamedPolygon('SWNODE3') Or  IsNamedPolygon('SWNODE3') Or  IsNamedPolygon('SWNODE4') Or  IsNamedPolygon('SWNODE2_1') Or  IsNamedPolygon('RTN') Or  IsNamedPolygon('SGND') Or  IsNamedPolygon('SWNODE2') Or  IsNamedPolygon('54V2') Or  IsNamedPolygon('SWNODE2') Or  IsNamedPolygon('T100_2') Or  IsNamedPolygon('SGND') Or  IsNamedPolygon('SGND') Or  IsNamedPolygon('SGND') Or  IsNamedPolygon('T100_1') Or  IsNamedPolygon('Iout_SNS') Or  IsNamedPolygon('54V2') Or  IsNamedPolygon('SWNODE4') Or  IsNamedPolygon('SWNODE3') Or  IsNamedPolygon('SGND')] p6: connectstyle=Direct reliefconductorwidth=10 reliefentries=4 polygonreliefangle="90 Angle" airgapwidth=10
PolygonConnect PolygonConnect_62 [All vs IsNamedPolygon('SWNODE4') Or  IsNamedPolygon('SWNODE3') Or  IsNamedPolygon('SWNODE3') Or  IsNamedPolygon('SWNODE3') Or  IsNamedPolygon('SWNODE3') Or  IsNamedPolygon('SWNODE3') Or  IsNamedPolygon('SWNODE3') Or  IsNamedPolygon('T100_1') Or  IsNamedPolygon('SGND') Or  IsNamedPolygon('5Vs') Or  IsNamedPolygon('Iout_SNS') Or  IsNamedPolygon('SGND') Or  IsNamedPolygon('SGND') Or  IsNamedPolygon('54V1') Or  IsNamedPolygon('SGND') Or  IsNamedPolygon('54V2') Or  IsNamedPolygon('RTN') Or  IsNamedPolygon('NetT100_2') Or  IsNamedPolygon('54V2') Or  IsNamedPolygon('SWNODE2') Or  IsNamedPolygon('PGND') Or  IsNamedPolygon('Iout_SNS') Or  IsNamedPolygon('SWNODE3') Or  IsNamedPolygon('VSR') Or  IsNamedPolygon('Iout_SNS') Or  IsNamedPolygon('PGND') Or  IsNamedPolygon('NetT100_1') Or  IsNamedPolygon('54V1') Or  IsNamedPolygon('NetT100_2') Or  IsNamedPolygon('VSR') Or  IsNamedPolygon('PGND') Or  IsNamedPolygon('NetT100_1') Or  IsNamedPolygon('NetT100_2') Or  IsNamedPolygon('54V1') Or  IsNamedPolygon('SGND') Or  IsNamedPolygon('SWNODE2') Or  IsNamedPolygon('SWNODE2') Or  IsNamedPolygon('54V1') Or  IsNamedPolygon('54V2') Or  IsNamedPolygon('NetT100_2') Or  IsNamedPolygon('54V2') Or  IsNamedPolygon('NetT100_1') Or  IsNamedPolygon('SWNODE2') Or  IsNamedPolygon('SGND') Or  IsNamedPolygon('54V1') Or  IsNamedPolygon('NetT100_1') Or  IsNamedPolygon('SGND') Or  IsNamedPolygon('VSR') Or  IsNamedPolygon('SGND') Or  IsNamedPolygon('SWNODE1_1') Or  IsNamedPolygon('Iout_SNS') Or  IsNamedPolygon('VSR') Or  IsNamedPolygon('54V1') Or  IsNamedPolygon('Iout_SNS') Or  IsNamedPolygon('SWNODE2') Or  IsNamedPolygon('SGND') Or  IsNamedPolygon('SWNODE2_1') Or  IsNamedPolygon('54V2') Or  IsNamedPolygon('NetT100_1') Or  IsNamedPolygon('NetT100_2') Or  IsNamedPolygon('NetT100_2') Or  IsNamedPolygon('NetT100_1') Or  IsNamedPolygon('SWNODE1_1') Or  IsNamedPolygon('SWNODE2_1') Or  IsNamedPolygon('T100_1') Or  IsNamedPolygon('L200_1') Or  IsNamedPolygon('54V2') Or  IsNamedPolygon('VSR') Or  IsNamedPolygon('VSR') Or  IsNamedPolygon('SGND') Or  IsNamedPolygon('Iout_SNS') Or  IsNamedPolygon('SGND') Or  IsNamedPolygon('SGND') Or  IsNamedPolygon('VBB') Or  IsNamedPolygon('SWNODE4') Or  IsNamedPolygon('SWNODE4') Or  IsNamedPolygon('SWNODE4') Or  IsNamedPolygon('SWNODE4') Or  IsNamedPolygon('SWNODE4')] p7: connectstyle=Direct reliefconductorwidth=10 reliefentries=4 polygonreliefangle="90 Angle" airgapwidth=10
PolygonConnect PolygonConnect_61 [All vs IsNamedPolygon('54V2') Or  IsNamedPolygon('PGND') Or  IsNamedPolygon('54V2') Or  IsNamedPolygon('L200_1') Or  IsNamedPolygon('NetT100_1') Or  IsNamedPolygon('Iout_SNS') Or  IsNamedPolygon('SWNODE2') Or  IsNamedPolygon('54V1') Or  IsNamedPolygon('SWNODE1_1') Or  IsNamedPolygon('54V2') Or  IsNamedPolygon('VBB') Or  IsNamedPolygon('PGND') Or  IsNamedPolygon('54V1') Or  IsNamedPolygon('SWNODE2') Or  IsNamedPolygon('SGND') Or  IsNamedPolygon('NetT100_2') Or  IsNamedPolygon('PGND') Or  IsNamedPolygon('54V2') Or  IsNamedPolygon('Iout_SNS') Or  IsNamedPolygon('NetT100_1') Or  IsNamedPolygon('SGND') Or  IsNamedPolygon('54V2') Or  IsNamedPolygon('SGND') Or  IsNamedPolygon('NetT100_1') Or  IsNamedPolygon('SWNODE2') Or  IsNamedPolygon('SWNODE2') Or  IsNamedPolygon('SGND') Or  IsNamedPolygon('SGND') Or  IsNamedPolygon('SGND') Or  IsNamedPolygon('NetT100_2') Or  IsNamedPolygon('SGND') Or  IsNamedPolygon('VSR') Or  IsNamedPolygon('VSR') Or  IsNamedPolygon('54V1') Or  IsNamedPolygon('SGND') Or  IsNamedPolygon('SGND') Or  IsNamedPolygon('NetT100_1') Or  IsNamedPolygon('NetT100_1') Or  IsNamedPolygon('NetT100_1') Or  IsNamedPolygon('Iout_SNS') Or  IsNamedPolygon('NetT100_2') Or  IsNamedPolygon('NetT100_2') Or  IsNamedPolygon('SWNODE2') Or  IsNamedPolygon('SWNODE2_1') Or  IsNamedPolygon('Iout_SNS') Or  IsNamedPolygon('54V1') Or  IsNamedPolygon('SGND') Or  IsNamedPolygon('NetT100_2') Or  IsNamedPolygon('Iout_SNS') Or  IsNamedPolygon('Iout_SNS') Or  IsNamedPolygon('SGND') Or  IsNamedPolygon('SWNODE2_1') Or  IsNamedPolygon('VSR') Or  IsNamedPolygon('NetT100_2') Or  IsNamedPolygon('54V2') Or  IsNamedPolygon('54V1') Or  IsNamedPolygon('SWNODE1_1') Or  IsNamedPolygon('SGND') Or  IsNamedPolygon('54V1') Or  IsNamedPolygon('RTN') Or  IsNamedPolygon('T100_1') Or  IsNamedPolygon('5Vs') Or  IsNamedPolygon('VSR') Or  IsNamedPolygon('SWNODE3') Or  IsNamedPolygon('SWNODE4') Or  IsNamedPolygon('SWNODE3') Or  IsNamedPolygon('SWNODE4') Or  IsNamedPolygon('VSR') Or  IsNamedPolygon('SWNODE4') Or  IsNamedPolygon('SWNODE3') Or  IsNamedPolygon('SWNODE4') Or  IsNamedPolygon('SWNODE4') Or  IsNamedPolygon('SWNODE3') Or  IsNamedPolygon('VSR') Or  IsNamedPolygon('SWNODE3') Or  IsNamedPolygon('SWNODE4') Or  IsNamedPolygon('SWNODE3')] p8: connectstyle=Direct reliefconductorwidth=10 reliefentries=4 polygonreliefangle="90 Angle" airgapwidth=10
PolygonConnect PolygonConnect_60 [All vs IsNamedPolygon('RTN') Or  IsNamedPolygon('54V1') Or  IsNamedPolygon('NetT100_2') Or  IsNamedPolygon('VBB') Or  IsNamedPolygon('SWNODE1_1') Or  IsNamedPolygon('SGND') Or  IsNamedPolygon('SGND') Or  IsNamedPolygon('PGND') Or  IsNamedPolygon('SWNODE4') Or  IsNamedPolygon('SWNODE2') Or  IsNamedPolygon('Iout_SNS') Or  IsNamedPolygon('SWNODE1_1') Or  IsNamedPolygon('NetT100_2') Or  IsNamedPolygon('NetT100_2') Or  IsNamedPolygon('SWNODE4') Or  IsNamedPolygon('SWNODE4') Or  IsNamedPolygon('NetT100_1') Or  IsNamedPolygon('SWNODE3') Or  IsNamedPolygon('SGND') Or  IsNamedPolygon('SWNODE4') Or  IsNamedPolygon('NetT100_1') Or  IsNamedPolygon('54V1') Or  IsNamedPolygon('SWNODE3') Or  IsNamedPolygon('SWNODE4') Or  IsNamedPolygon('SWNODE2') Or  IsNamedPolygon('VSR') Or  IsNamedPolygon('54V2') Or  IsNamedPolygon('SWNODE3') Or  IsNamedPolygon('NetT100_2') Or  IsNamedPolygon('NetT100_2') Or  IsNamedPolygon('54V1') Or  IsNamedPolygon('VSR') Or  IsNamedPolygon('54V2') Or  IsNamedPolygon('VSR') Or  IsNamedPolygon('SWNODE3') Or  IsNamedPolygon('SWNODE3') Or  IsNamedPolygon('VSR') Or  IsNamedPolygon('VSR') Or  IsNamedPolygon('NetT100_1') Or  IsNamedPolygon('NetT100_1') Or  IsNamedPolygon('SWNODE3') Or  IsNamedPolygon('NetT100_1') Or  IsNamedPolygon('SGND') Or  IsNamedPolygon('NetT100_2') Or  IsNamedPolygon('SWNODE2') Or  IsNamedPolygon('SWNODE2') Or  IsNamedPolygon('PGND') Or  IsNamedPolygon('VSR') Or  IsNamedPolygon('SWNODE2_1') Or  IsNamedPolygon('SWNODE4') Or  IsNamedPolygon('5Vs') Or  IsNamedPolygon('54V1') Or  IsNamedPolygon('L200_1') Or  IsNamedPolygon('PGND') Or  IsNamedPolygon('SGND') Or  IsNamedPolygon('NetT100_1') Or  IsNamedPolygon('Iout_SNS') Or  IsNamedPolygon('SGND') Or  IsNamedPolygon('SWNODE2') Or  IsNamedPolygon('Iout_SNS') Or  IsNamedPolygon('SWNODE2_1') Or  IsNamedPolygon('SGND') Or  IsNamedPolygon('SGND') Or  IsNamedPolygon('SGND') Or  IsNamedPolygon('SGND') Or  IsNamedPolygon('Iout_SNS') Or  IsNamedPolygon('54V1') Or  IsNamedPolygon('Iout_SNS') Or  IsNamedPolygon('54V1') Or  IsNamedPolygon('54V2') Or  IsNamedPolygon('SGND') Or  IsNamedPolygon('Iout_SNS') Or  IsNamedPolygon('SGND') Or  IsNamedPolygon('54V2') Or  IsNamedPolygon('54V2') Or  IsNamedPolygon('54V2') Or  IsNamedPolygon('SGND')] p9: connectstyle=Direct reliefconductorwidth=10 reliefentries=4 polygonreliefangle="90 Angle" airgapwidth=10
PolygonConnect PolygonConnect_59 [All vs IsNamedPolygon('PGND') Or  IsNamedPolygon('PGND') Or  IsNamedPolygon('NetT100_1') Or  IsNamedPolygon('SWNODE3') Or  IsNamedPolygon('SWNODE4') Or  IsNamedPolygon('PGND') Or  IsNamedPolygon('VBB') Or  IsNamedPolygon('NetT100_1') Or  IsNamedPolygon('NetT100_1') Or  IsNamedPolygon('SWNODE3') Or  IsNamedPolygon('54V2') Or  IsNamedPolygon('VSR') Or  IsNamedPolygon('VSR') Or  IsNamedPolygon('VSR') Or  IsNamedPolygon('54V1') Or  IsNamedPolygon('PGND') Or  IsNamedPolygon('SWNODE2') Or  IsNamedPolygon('PGND') Or  IsNamedPolygon('Iout_SNS') Or  IsNamedPolygon('SWNODE3') Or  IsNamedPolygon('SWNODE3') Or  IsNamedPolygon('SWNODE3') Or  IsNamedPolygon('NetT100_1') Or  IsNamedPolygon('NetT100_2') Or  IsNamedPolygon('NetT100_1') Or  IsNamedPolygon('NetT100_1') Or  IsNamedPolygon('VSR') Or  IsNamedPolygon('54V1') Or  IsNamedPolygon('54V2') Or  IsNamedPolygon('SWNODE4') Or  IsNamedPolygon('VSR') Or  IsNamedPolygon('SWNODE4') Or  IsNamedPolygon('54V1') Or  IsNamedPolygon('SWNODE2') Or  IsNamedPolygon('VSR') Or  IsNamedPolygon('ACL_GND') Or  IsNamedPolygon('SWNODE3') Or  IsNamedPolygon('NetT100_2') Or  IsNamedPolygon('NetT100_2') Or  IsNamedPolygon('NetT100_2') Or  IsNamedPolygon('NetT100_2') Or  IsNamedPolygon('NetT100_2') Or  IsNamedPolygon('Iout_SNS') Or  IsNamedPolygon('ACL_GND') Or  IsNamedPolygon('PGND') Or  IsNamedPolygon('SWNODE4') Or  IsNamedPolygon('SWNODE4') Or  IsNamedPolygon('SWNODE4') Or  IsNamedPolygon('SGND') Or  IsNamedPolygon('SWNODE2') Or  IsNamedPolygon('SGND') Or  IsNamedPolygon('SGND') Or  IsNamedPolygon('5Vs') Or  IsNamedPolygon('VBB') Or  IsNamedPolygon('SGND') Or  IsNamedPolygon('5Vs') Or  IsNamedPolygon('Iout_SNS') Or  IsNamedPolygon('SGND') Or  IsNamedPolygon('SGND') Or  IsNamedPolygon('Iout_SNS') Or  IsNamedPolygon('SWNODE2') Or  IsNamedPolygon('54V1') Or  IsNamedPolygon('SGND') Or  IsNamedPolygon('ACL_GND') Or  IsNamedPolygon('Iout_SNS') Or  IsNamedPolygon('SWNODE1_1') Or  IsNamedPolygon('54V1') Or  IsNamedPolygon('SGND') Or  IsNamedPolygon('SGND') Or  IsNamedPolygon('54V2') Or  IsNamedPolygon('SGND') Or  IsNamedPolygon('5Vs') Or  IsNamedPolygon('54V2') Or  IsNamedPolygon('SWNODE1_1') Or  IsNamedPolygon('L200_1') Or  IsNamedPolygon('VBB') Or  IsNamedPolygon('SWNODE2') Or  IsNamedPolygon('54V2') Or  IsNamedPolygon('SGND') Or  IsNamedPolygon('Iout_SNS') Or  IsNamedPolygon('SGND') Or  IsNamedPolygon('SGND') Or  IsNamedPolygon('SGND') Or  IsNamedPolygon('PGND') Or  IsNamedPolygon('SWNODE2') Or  IsNamedPolygon('54V1') Or  IsNamedPolygon('15Vs') Or  IsNamedPolygon('PGND') Or  IsNamedPolygon('SWNODE2') Or  IsNamedPolygon('PGND') Or  IsNamedPolygon('54V2') Or  IsNamedPolygon('SGND') Or  IsNamedPolygon('SWNODE2_1')] p10: connectstyle=Direct reliefconductorwidth=10 reliefentries=4 polygonreliefangle="90 Angle" airgapwidth=10
PolygonConnect PolygonConnect_58 [All vs IsNamedPolygon('SWNODE4') Or  IsNamedPolygon('SWNODE3') Or  IsNamedPolygon('SWNODE3') Or  IsNamedPolygon('SWNODE3') Or  IsNamedPolygon('VSR') Or  IsNamedPolygon('VSR') Or  IsNamedPolygon('SWNODE3') Or  IsNamedPolygon('SWNODE4') Or  IsNamedPolygon('VSR') Or  IsNamedPolygon('SGND') Or  IsNamedPolygon('ACL_GND') Or  IsNamedPolygon('SWNODE4') Or  IsNamedPolygon('VSR') Or  IsNamedPolygon('SWNODE4') Or  IsNamedPolygon('VSR') Or  IsNamedPolygon('SWNODE3') Or  IsNamedPolygon('SWNODE4') Or  IsNamedPolygon('VSR') Or  IsNamedPolygon('SWNODE4') Or  IsNamedPolygon('SWNODE3') Or  IsNamedPolygon('54V2') Or  IsNamedPolygon('15Vs') Or  IsNamedPolygon('SGND') Or  IsNamedPolygon('Iout_SNS') Or  IsNamedPolygon('SGND') Or  IsNamedPolygon('VBB') Or  IsNamedPolygon('Iout_SNS') Or  IsNamedPolygon('PGND') Or  IsNamedPolygon('PGND') Or  IsNamedPolygon('54V2') Or  IsNamedPolygon('54V2') Or  IsNamedPolygon('54V1') Or  IsNamedPolygon('VBB') Or  IsNamedPolygon('54V2') Or  IsNamedPolygon('Iout_SNS') Or  IsNamedPolygon('VBB') Or  IsNamedPolygon('SGND') Or  IsNamedPolygon('SGND') Or  IsNamedPolygon('54V1') Or  IsNamedPolygon('SGND') Or  IsNamedPolygon('Iout_SNS') Or  IsNamedPolygon('Iout_SNS') Or  IsNamedPolygon('PGND') Or  IsNamedPolygon('SGND') Or  IsNamedPolygon('54V2') Or  IsNamedPolygon('SGND') Or  IsNamedPolygon('54V1') Or  IsNamedPolygon('SGND') Or  IsNamedPolygon('SGND') Or  IsNamedPolygon('ACL_GND') Or  IsNamedPolygon('54V1') Or  IsNamedPolygon('PGND') Or  IsNamedPolygon('PGND') Or  IsNamedPolygon('PGND') Or  IsNamedPolygon('VBB') Or  IsNamedPolygon('SWNODE2') Or  IsNamedPolygon('PGND') Or  IsNamedPolygon('SWNODE2') Or  IsNamedPolygon('Iout_SNS') Or  IsNamedPolygon('PGND') Or  IsNamedPolygon('VBB') Or  IsNamedPolygon('NetT100_2') Or  IsNamedPolygon('NetT100_2') Or  IsNamedPolygon('54V1') Or  IsNamedPolygon('54V1') Or  IsNamedPolygon('NetT100_1') Or  IsNamedPolygon('NetT100_2') Or  IsNamedPolygon('NetT100_1') Or  IsNamedPolygon('NetT100_1') Or  IsNamedPolygon('SWNODE2') Or  IsNamedPolygon('NetT100_1') Or  IsNamedPolygon('ACL_GND') Or  IsNamedPolygon('NetT100_2') Or  IsNamedPolygon('NetT100_2') Or  IsNamedPolygon('SWNODE2') Or  IsNamedPolygon('VBB') Or  IsNamedPolygon('54V2') Or  IsNamedPolygon('NetT100_1') Or  IsNamedPolygon('PGND') Or  IsNamedPolygon('NetT100_1') Or  IsNamedPolygon('VBB') Or  IsNamedPolygon('PGND') Or  IsNamedPolygon('NetT100_2')] p11: connectstyle=Direct reliefconductorwidth=10 reliefentries=4 polygonreliefangle="90 Angle" airgapwidth=10
PolygonConnect PolygonConnect_57 [All vs IsNamedPolygon('SWNODE2') Or  IsNamedPolygon('NetT100_1') Or  IsNamedPolygon('ACL_GND') Or  IsNamedPolygon('54V2') Or  IsNamedPolygon('PGND') Or  IsNamedPolygon('54V2') Or  IsNamedPolygon('Iout_SNS') Or  IsNamedPolygon('PGND') Or  IsNamedPolygon('SWNODE4') Or  IsNamedPolygon('Iout_SNS') Or  IsNamedPolygon('VBB') Or  IsNamedPolygon('SWNODE2') Or  IsNamedPolygon('VSR') Or  IsNamedPolygon('NetT100_1') Or  IsNamedPolygon('NetT100_2') Or  IsNamedPolygon('54V1') Or  IsNamedPolygon('NetT100_2') Or  IsNamedPolygon('SGND') Or  IsNamedPolygon('NetT100_2') Or  IsNamedPolygon('54V1') Or  IsNamedPolygon('54V2') Or  IsNamedPolygon('SWNODE2') Or  IsNamedPolygon('Iout_SNS') Or  IsNamedPolygon('SWNODE4') Or  IsNamedPolygon('PGND') Or  IsNamedPolygon('SWNODE4') Or  IsNamedPolygon('54V1') Or  IsNamedPolygon('54V1') Or  IsNamedPolygon('VSR') Or  IsNamedPolygon('VSR') Or  IsNamedPolygon('PGND') Or  IsNamedPolygon('PGND') Or  IsNamedPolygon('SWNODE3') Or  IsNamedPolygon('NetT100_1') Or  IsNamedPolygon('VSR') Or  IsNamedPolygon('Iout_SNS') Or  IsNamedPolygon('PGND') Or  IsNamedPolygon('54V1') Or  IsNamedPolygon('VSR') Or  IsNamedPolygon('SWNODE3') Or  IsNamedPolygon('SWNODE3') Or  IsNamedPolygon('NetT100_1') Or  IsNamedPolygon('54V1') Or  IsNamedPolygon('54V2') Or  IsNamedPolygon('NetT100_2') Or  IsNamedPolygon('SGND') Or  IsNamedPolygon('54V2') Or  IsNamedPolygon('NetT100_2') Or  IsNamedPolygon('SWNODE3') Or  IsNamedPolygon('SWNODE4') Or  IsNamedPolygon('VBB') Or  IsNamedPolygon('PGND') Or  IsNamedPolygon('SWNODE2') Or  IsNamedPolygon('ACL_GND') Or  IsNamedPolygon('SWNODE4') Or  IsNamedPolygon('VBB') Or  IsNamedPolygon('PGND') Or  IsNamedPolygon('SWNODE4') Or  IsNamedPolygon('NetT100_1') Or  IsNamedPolygon('NetT100_2') Or  IsNamedPolygon('54V2') Or  IsNamedPolygon('VBB') Or  IsNamedPolygon('Iout_SNS') Or  IsNamedPolygon('VBB') Or  IsNamedPolygon('Iout_SNS') Or  IsNamedPolygon('PGND') Or  IsNamedPolygon('NetT100_1') Or  IsNamedPolygon('SWNODE3') Or  IsNamedPolygon('VSR') Or  IsNamedPolygon('SGND') Or  IsNamedPolygon('SWNODE3') Or  IsNamedPolygon('VBB') Or  IsNamedPolygon('VBB') Or  IsNamedPolygon('PGND') Or  IsNamedPolygon('ACL_GND') Or  IsNamedPolygon('SGND') Or  IsNamedPolygon('SGND') Or  IsNamedPolygon('15Vs') Or  IsNamedPolygon('SGND') Or  IsNamedPolygon('SGND') Or  IsNamedPolygon('SGND')] p12: connectstyle=Direct reliefconductorwidth=10 reliefentries=4 polygonreliefangle="90 Angle" airgapwidth=10
PolygonConnect PolygonConnect_56 [All vs IsNamedPolygon('SWNODE3') Or  IsNamedPolygon('SWNODE3') Or  IsNamedPolygon('SWNODE4') Or  IsNamedPolygon('SGND') Or  IsNamedPolygon('ACL_GND') Or  IsNamedPolygon('VSR') Or  IsNamedPolygon('SGND') Or  IsNamedPolygon('NetT100_2') Or  IsNamedPolygon('Iout_SNS') Or  IsNamedPolygon('SWNODE2') Or  IsNamedPolygon('VBB') Or  IsNamedPolygon('PGND') Or  IsNamedPolygon('SWNODE4') Or  IsNamedPolygon('VSR') Or  IsNamedPolygon('NetT100_2') Or  IsNamedPolygon('SWNODE3') Or  IsNamedPolygon('VSR') Or  IsNamedPolygon('SWNODE2') Or  IsNamedPolygon('54V1') Or  IsNamedPolygon('SWNODE3') Or  IsNamedPolygon('VBB') Or  IsNamedPolygon('NetT100_1') Or  IsNamedPolygon('ACL_GND') Or  IsNamedPolygon('NetT100_1') Or  IsNamedPolygon('SWNODE2') Or  IsNamedPolygon('54V1') Or  IsNamedPolygon('SWNODE4') Or  IsNamedPolygon('NetT100_1') Or  IsNamedPolygon('SWNODE4') Or  IsNamedPolygon('VSR') Or  IsNamedPolygon('VBB') Or  IsNamedPolygon('54V1') Or  IsNamedPolygon('NetT100_2') Or  IsNamedPolygon('VSR') Or  IsNamedPolygon('NetT100_1') Or  IsNamedPolygon('SWNODE3') Or  IsNamedPolygon('SWNODE3') Or  IsNamedPolygon('SWNODE4') Or  IsNamedPolygon('NetT100_2') Or  IsNamedPolygon('PGND') Or  IsNamedPolygon('PGND') Or  IsNamedPolygon('PGND') Or  IsNamedPolygon('Iout_SNS') Or  IsNamedPolygon('54V2') Or  IsNamedPolygon('SWNODE2') Or  IsNamedPolygon('SWNODE4') Or  IsNamedPolygon('54V2') Or  IsNamedPolygon('VSR') Or  IsNamedPolygon('NetT100_2') Or  IsNamedPolygon('NetT100_1') Or  IsNamedPolygon('NetT100_1') Or  IsNamedPolygon('VBB') Or  IsNamedPolygon('NetT100_2')] p13: connectstyle=Direct reliefconductorwidth=10 reliefentries=4 polygonreliefangle="90 Angle" airgapwidth=10
PolygonConnect PolygonConnect_55 [All vs IsNamedPolygon('SWNODE2') Or  IsNamedPolygon('VSR') Or  IsNamedPolygon('SWNODE3') Or  IsNamedPolygon('SWNODE4') Or  IsNamedPolygon('SWNODE3') Or  IsNamedPolygon('VSR') Or  IsNamedPolygon('VBB') Or  IsNamedPolygon('SWNODE3') Or  IsNamedPolygon('PGND') Or  IsNamedPolygon('VSR') Or  IsNamedPolygon('SWNODE4') Or  IsNamedPolygon('VSR') Or  IsNamedPolygon('VBB') Or  IsNamedPolygon('SWNODE4') Or  IsNamedPolygon('SWNODE3') Or  IsNamedPolygon('SWNODE4') Or  IsNamedPolygon('VSR') Or  IsNamedPolygon('VBB') Or  IsNamedPolygon('SWNODE4') Or  IsNamedPolygon('SWNODE3') Or  IsNamedPolygon('SWNODE4') Or  IsNamedPolygon('SWNODE3') Or  IsNamedPolygon('VSR') Or  IsNamedPolygon('SGND') Or  IsNamedPolygon('ACL_GND') Or  IsNamedPolygon('VBB') Or  IsNamedPolygon('NetT100_2') Or  IsNamedPolygon('NetT100_1') Or  IsNamedPolygon('NetT100_1') Or  IsNamedPolygon('NetT100_2') Or  IsNamedPolygon('NetT100_2') Or  IsNamedPolygon('NetT100_1') Or  IsNamedPolygon('NetT100_1') Or  IsNamedPolygon('NetT100_1') Or  IsNamedPolygon('NetT100_2') Or  IsNamedPolygon('NetT100_1') Or  IsNamedPolygon('NetT100_2') Or  IsNamedPolygon('NetT100_2')] p14: connectstyle=Direct reliefconductorwidth=10 reliefentries=4 polygonreliefangle="90 Angle" airgapwidth=10
PolygonConnect PolygonConnect_54 [All vs IsNamedPolygon('12Vp') Or  IsNamedPolygon('SWNODE') Or  IsNamedPolygon('D403_2') Or  IsNamedPolygon('D403_2') Or  IsNamedPolygon('PGND') Or  IsNamedPolygon('BOTTOM_LAYER_NETC106_2_P030') Or  IsNamedPolygon('C102_1') Or  IsNamedPolygon('SGND') Or  IsNamedPolygon('TOP_LAYER_54V1_P046') Or  IsNamedPolygon('TOP_LAYER_54V2_P048') Or  IsNamedPolygon('TOP_LAYER_54V2_P048') Or  IsNamedPolygon('C108_1') Or  IsNamedPolygon('C108_1') Or  IsNamedPolygon('C108_1') Or  IsNamedPolygon('C108_1') Or  IsNamedPolygon('C108_1') Or  IsNamedPolygon('C108_1') Or  IsNamedPolygon('PGND') Or  IsNamedPolygon('ZCD') Or  IsNamedPolygon('Line') Or  IsNamedPolygon('5Vp') Or  IsNamedPolygon('12Vp') Or  IsNamedPolygon('T200_4') Or  IsNamedPolygon('T200_6') Or  IsNamedPolygon('SWNODE3') Or  IsNamedPolygon('T200_4') Or  IsNamedPolygon('T200_6') Or  IsNamedPolygon('SWNODE4') Or  IsNamedPolygon('VSR') Or  IsNamedPolygon('TOP_LAYER_IOUT_SNS_P092') Or  IsNamedPolygon('SIGNAL_LAYER_2_VBB_P094') Or  IsNamedPolygon('Vbulk1') Or  IsNamedPolygon('TOP_LAYER_VBULK_P104') Or  IsNamedPolygon('SIGNAL_LAYER_1_VBULK1_P106') Or  IsNamedPolygon('Line') Or  IsNamedPolygon('Line') Or  IsNamedPolygon('D404_2') Or  IsNamedPolygon('Vbulk') Or  IsNamedPolygon('D400_2') Or  IsNamedPolygon('SGND') Or  IsNamedPolygon('PGND') Or  IsNamedPolygon('TOP_LAYER_12VS_P126') Or  IsNamedPolygon('LEG3_HS_DRV') Or  IsNamedPolygon('LEG4_LS_DRV') Or  IsNamedPolygon('LEG4_HS_DRV') Or  IsNamedPolygon('SWNODE4') Or  IsNamedPolygon('SWNODE3') Or  IsNamedPolygon('T200_6') Or  IsNamedPolygon('T200_4') Or  IsNamedPolygon('VBB') Or  IsNamedPolygon('5Vs') Or  IsNamedPolygon('SGND') Or  IsNamedPolygon('Iout_SNS') Or  IsNamedPolygon('SGND') Or  IsNamedPolygon('SWNODE3') Or  IsNamedPolygon('SWNODE3') Or  IsNamedPolygon('SWNODE3') Or  IsNamedPolygon('SWNODE3') Or  IsNamedPolygon('SGND') Or  IsNamedPolygon('SGND') Or  IsNamedPolygon('SGND') Or  IsNamedPolygon('SWNODE4') Or  IsNamedPolygon('SWNODE4') Or  IsNamedPolygon('SWNODE4') Or  IsNamedPolygon('VSR') Or  IsNamedPolygon('SWNODE3') Or  IsNamedPolygon('SGND') Or  IsNamedPolygon('SGND') Or  IsNamedPolygon('SGND') Or  IsNamedPolygon('SGND') Or  IsNamedPolygon('SGND') Or  IsNamedPolygon('SGND') Or  IsNamedPolygon('54V1') Or  IsNamedPolygon('SGND') Or  IsNamedPolygon('VSR') Or  IsNamedPolygon('C102_1') Or  IsNamedPolygon('C102_1') Or  IsNamedPolygon('C102_1') Or  IsNamedPolygon('C102_1') Or  IsNamedPolygon('C102_1') Or  IsNamedPolygon('ZCD') Or  IsNamedPolygon('PGND') Or  IsNamedPolygon('PGND') Or  IsNamedPolygon('Vbulk1') Or  IsNamedPolygon('Vbulk') Or  IsNamedPolygon('Vbulk1') Or  IsNamedPolygon('Vbulk1') Or  IsNamedPolygon('ZCD') Or  IsNamedPolygon('Neutral') Or  IsNamedPolygon('Neutral') Or  IsNamedPolygon('C106_2') Or  IsNamedPolygon('C106_2') Or  IsNamedPolygon('C106_2') Or  IsNamedPolygon('SWNODE') Or  IsNamedPolygon('Vbulk1') Or  IsNamedPolygon('Earth1') Or  IsNamedPolygon('Earth1') Or  IsNamedPolygon('Earth1') Or  IsNamedPolygon('Earth1') Or  IsNamedPolygon('Earth1') Or  IsNamedPolygon('Earth1') Or  IsNamedPolygon('ZCD') Or  IsNamedPolygon('VBB') Or  IsNamedPolygon('PGND') Or  IsNamedPolygon('D106_1') Or  IsNamedPolygon('PGND') Or  IsNamedPolygon('PGND') Or  IsNamedPolygon('D106_1') Or  IsNamedPolygon('Vbulk') Or  IsNamedPolygon('D106_1') Or  IsNamedPolygon('PGND') Or  IsNamedPolygon('VBB') Or  IsNamedPolygon('VBB') Or  IsNamedPolygon('PGND') Or  IsNamedPolygon('PGND') Or  IsNamedPolygon('PGND') Or  IsNamedPolygon('PGND') Or  IsNamedPolygon('PGND') Or  IsNamedPolygon('ZCD') Or  IsNamedPolygon('ZCD') Or  IsNamedPolygon('C412_2') Or  IsNamedPolygon('VBB') Or  IsNamedPolygon('PGND') Or  IsNamedPolygon('PGND') Or  IsNamedPolygon('PGND') Or  IsNamedPolygon('PGND') Or  IsNamedPolygon('PGND') Or  IsNamedPolygon('PGND') Or  IsNamedPolygon('PGND') Or  IsNamedPolygon('Vbulk') Or  IsNamedPolygon('D404_2') Or  IsNamedPolygon('PGND') Or  IsNamedPolygon('Iout_SNS') Or  IsNamedPolygon('54V2') Or  IsNamedPolygon('54V2') Or  IsNamedPolygon('54V2') Or  IsNamedPolygon('54V2') Or  IsNamedPolygon('VSR') Or  IsNamedPolygon('VSR') Or  IsNamedPolygon('Iout_SNS') Or  IsNamedPolygon('SGND') Or  IsNamedPolygon('SGND') Or  IsNamedPolygon('BOTTOM_LAYER_54V1_P154') Or  IsNamedPolygon('ZCD') Or  IsNamedPolygon('PGND')] p15: connectstyle=Direct reliefconductorwidth=10 reliefentries=4 polygonreliefangle="90 Angle" airgapwidth=10
PolygonConnect PolygonConnect_53 [All vs IsNamedPolygon('BOTTOM_LAYER_54V1_P350')] p16: connectstyle=Direct reliefconductorwidth=10 reliefentries=4 polygonreliefangle="90 Angle" airgapwidth=10
PolygonConnect PolygonConnect_52 [All vs IsNamedPolygon('TOP_LAYER_54V1_P046')] p17: connectstyle=Direct reliefconductorwidth=10 reliefentries=4 polygonreliefangle="90 Angle" airgapwidth=10
PolygonConnect PolygonConnect_51 [All vs IsNamedPolygon('SIGNAL_LAYER_1_VBULK1_P106')] p18: connectstyle=Direct reliefconductorwidth=10 reliefentries=4 polygonreliefangle="90 Angle" airgapwidth=10
PolygonConnect PolygonConnect_50 [All vs IsNamedPolygon('BOTTOM_LAYER_54V1_P128')] p19: connectstyle=Direct reliefconductorwidth=10 reliefentries=4 polygonreliefangle="90 Angle" airgapwidth=10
